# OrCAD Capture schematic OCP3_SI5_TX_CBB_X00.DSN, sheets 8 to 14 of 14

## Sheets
8 PAGE08 - POWER SEQUENCE: size Custom
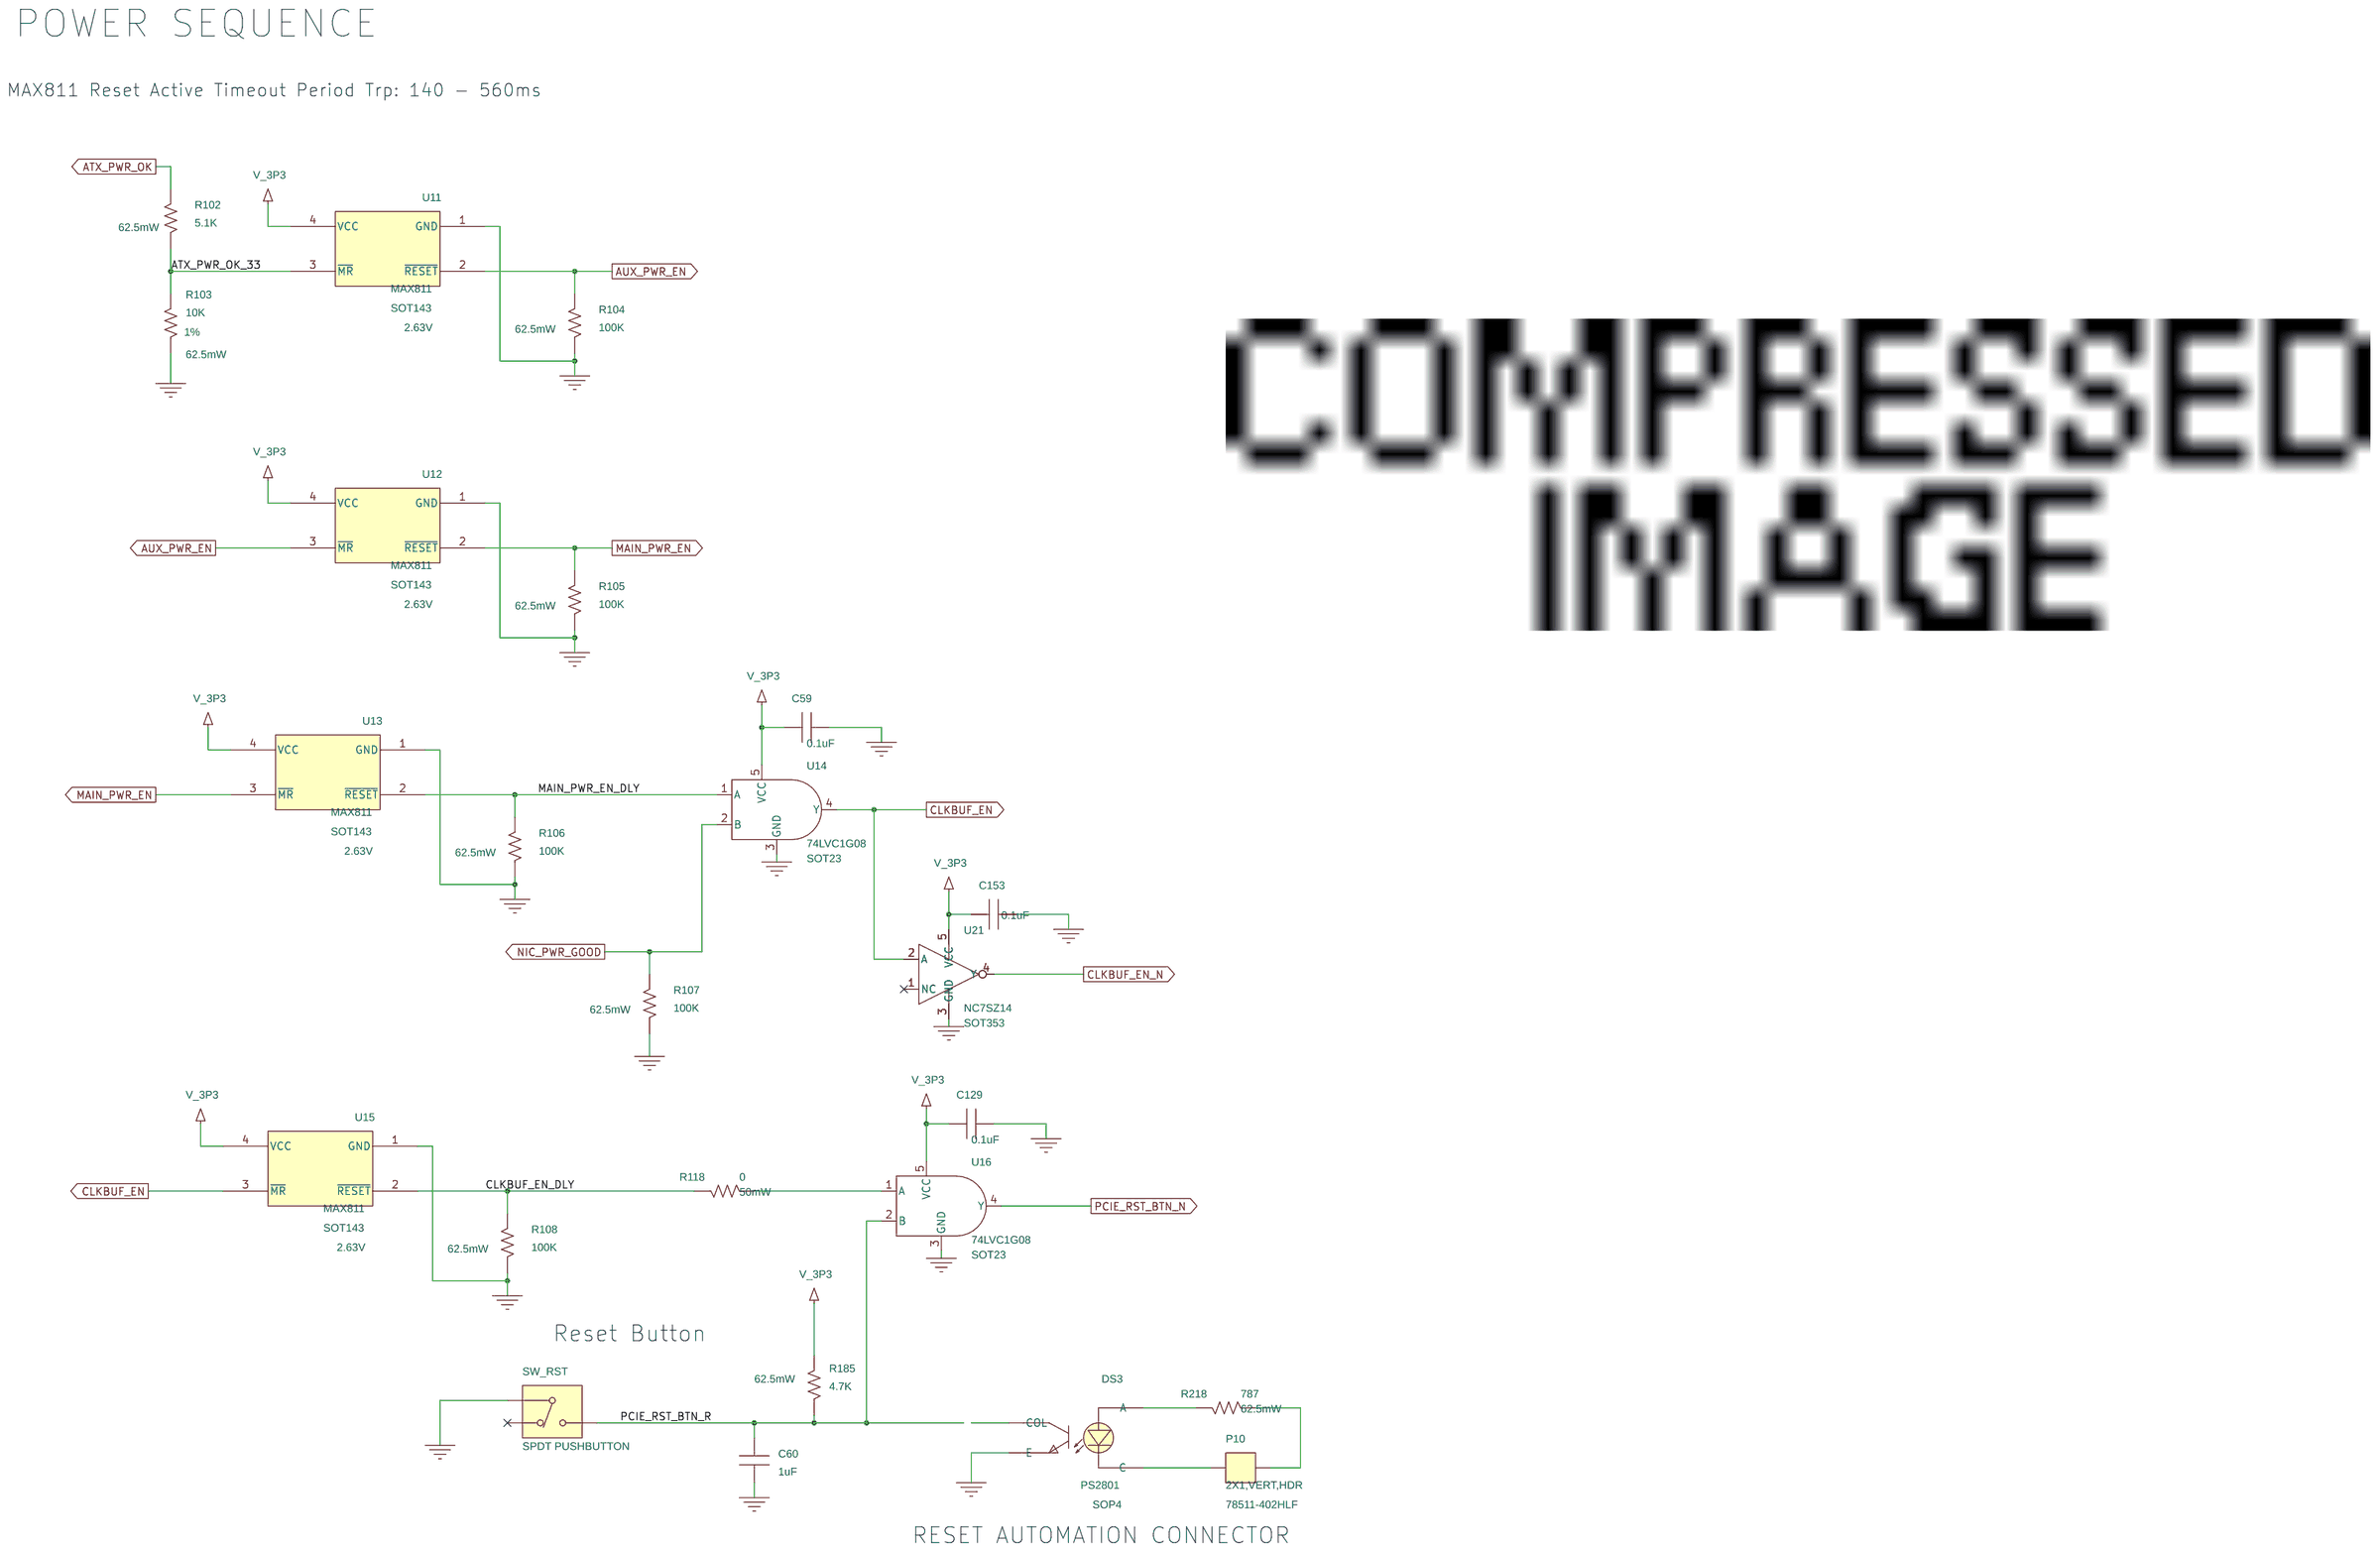
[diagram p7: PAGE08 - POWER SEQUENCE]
9 PAGE09 - PCIE LANES 0-3: size Custom
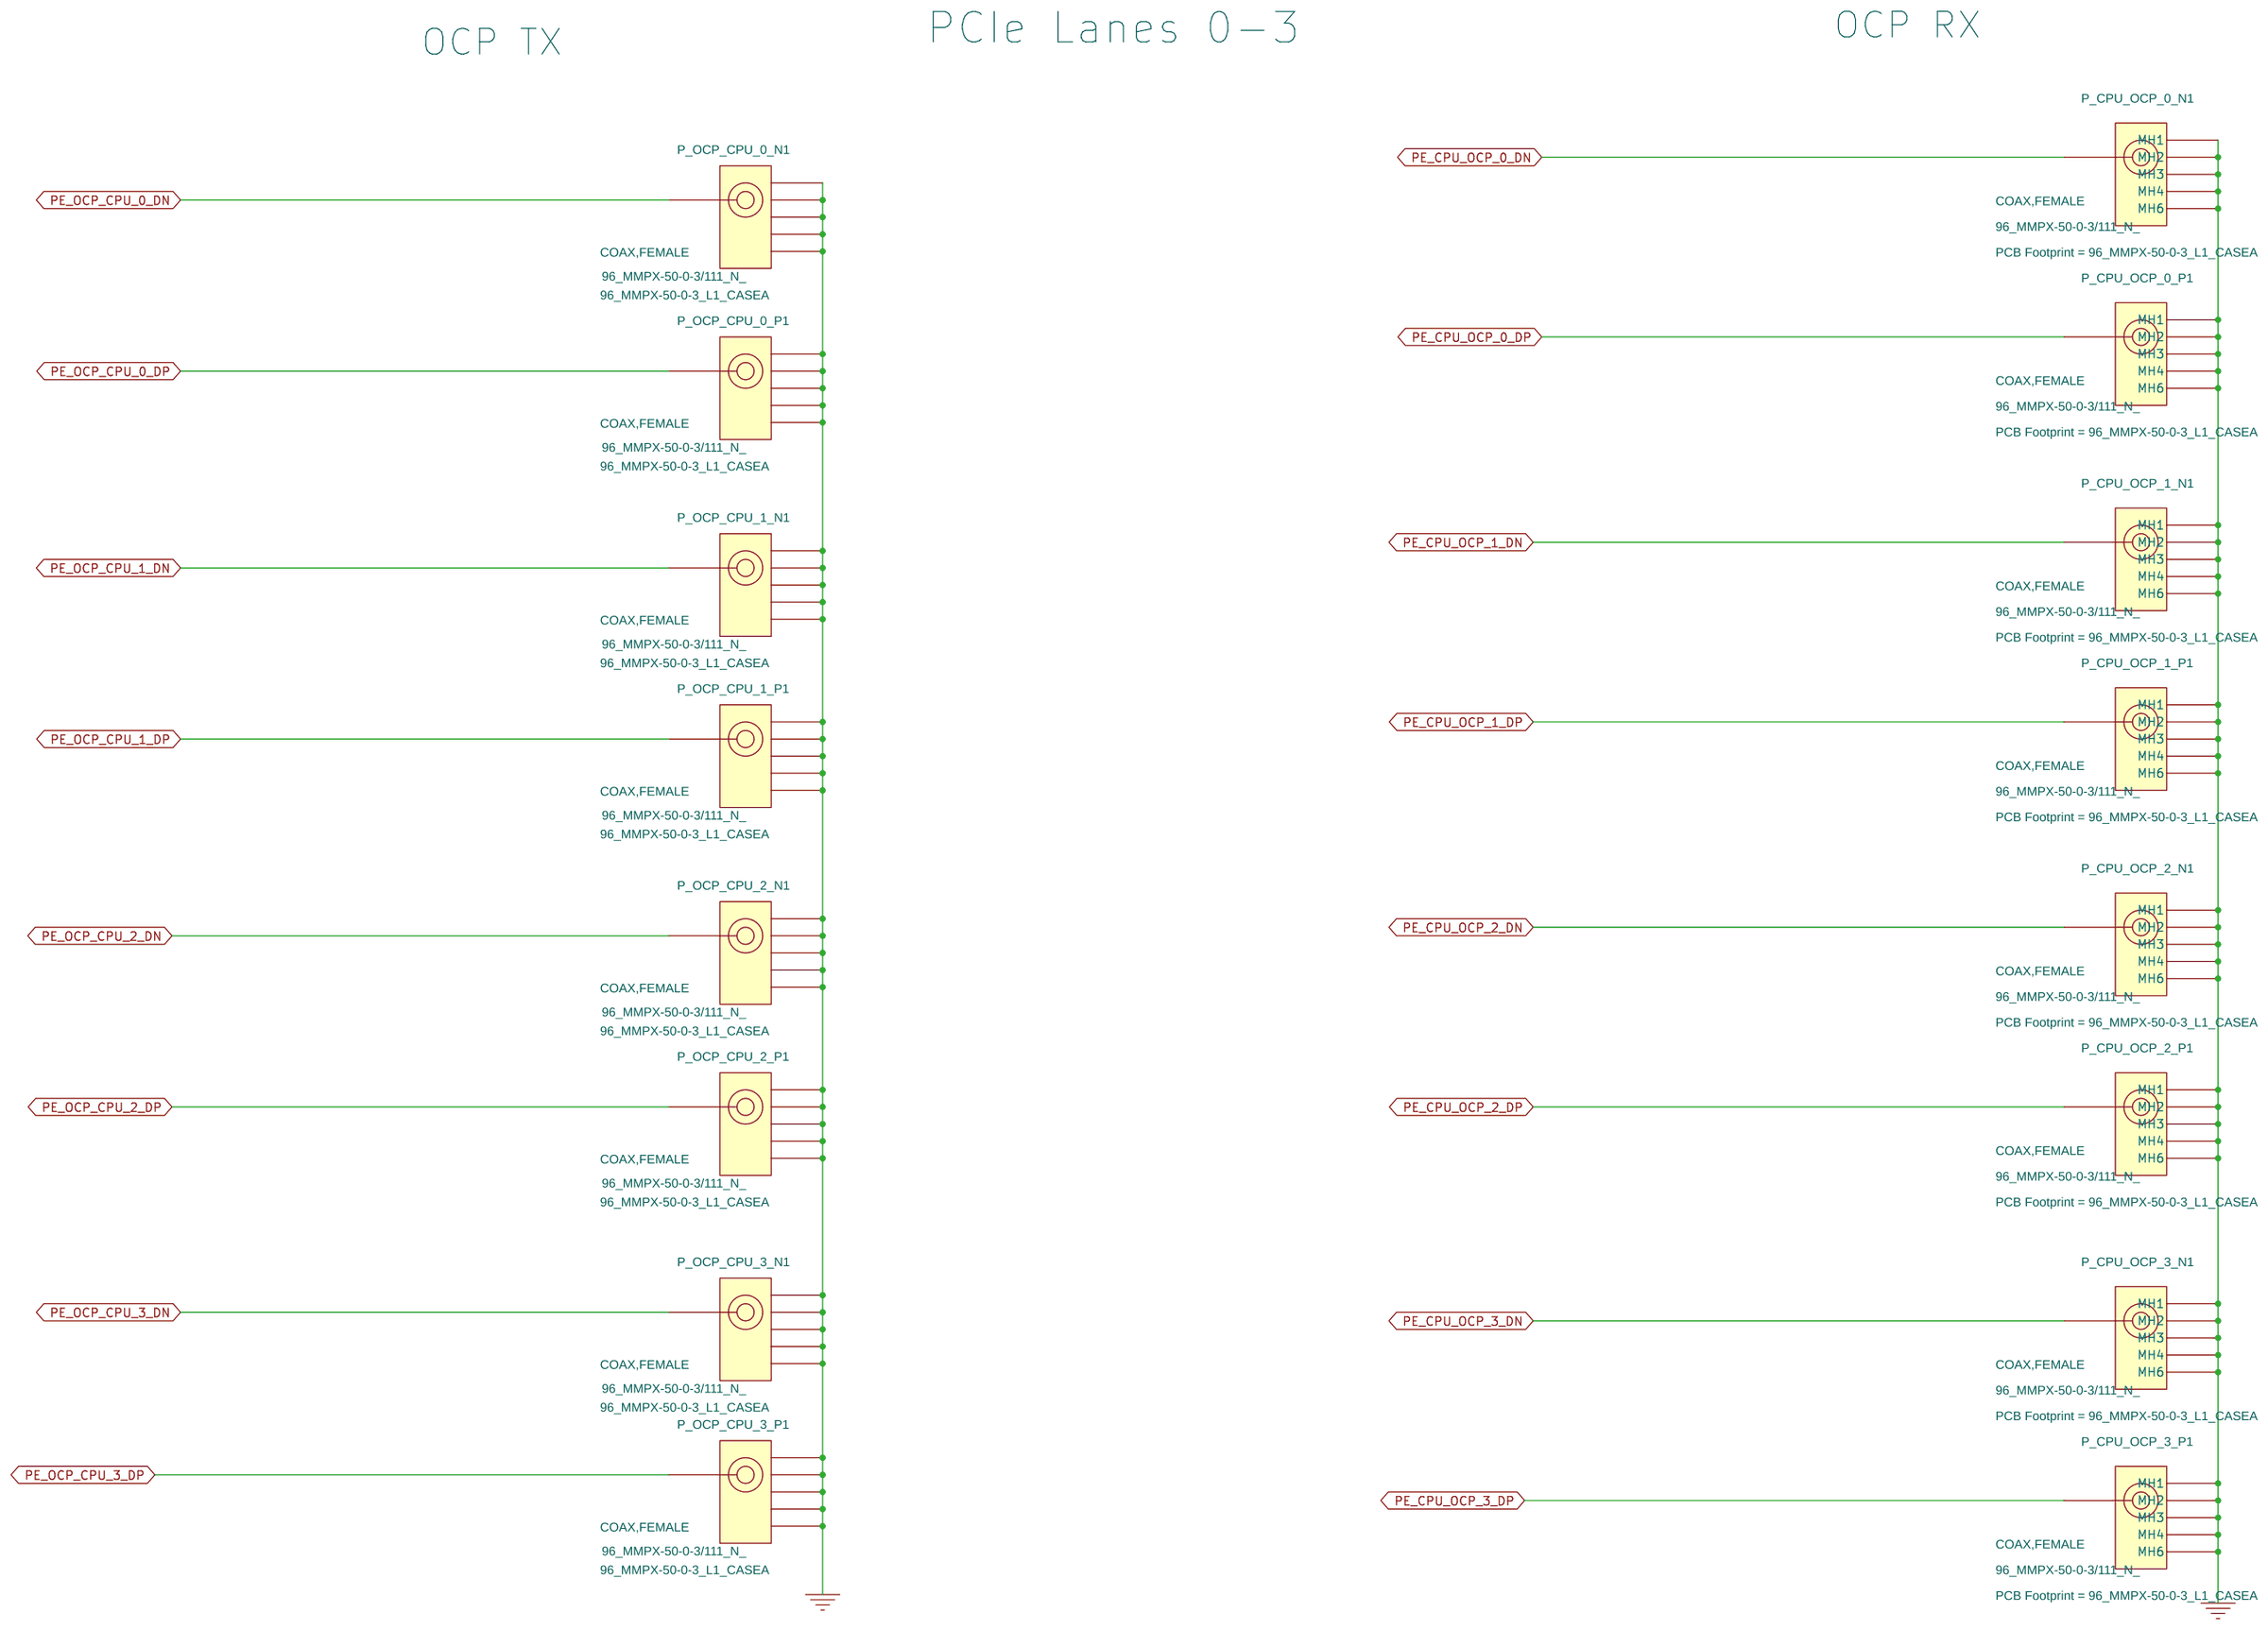
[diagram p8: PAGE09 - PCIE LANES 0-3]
10 PAGE10 - PCIE LANES 4-7: size Custom
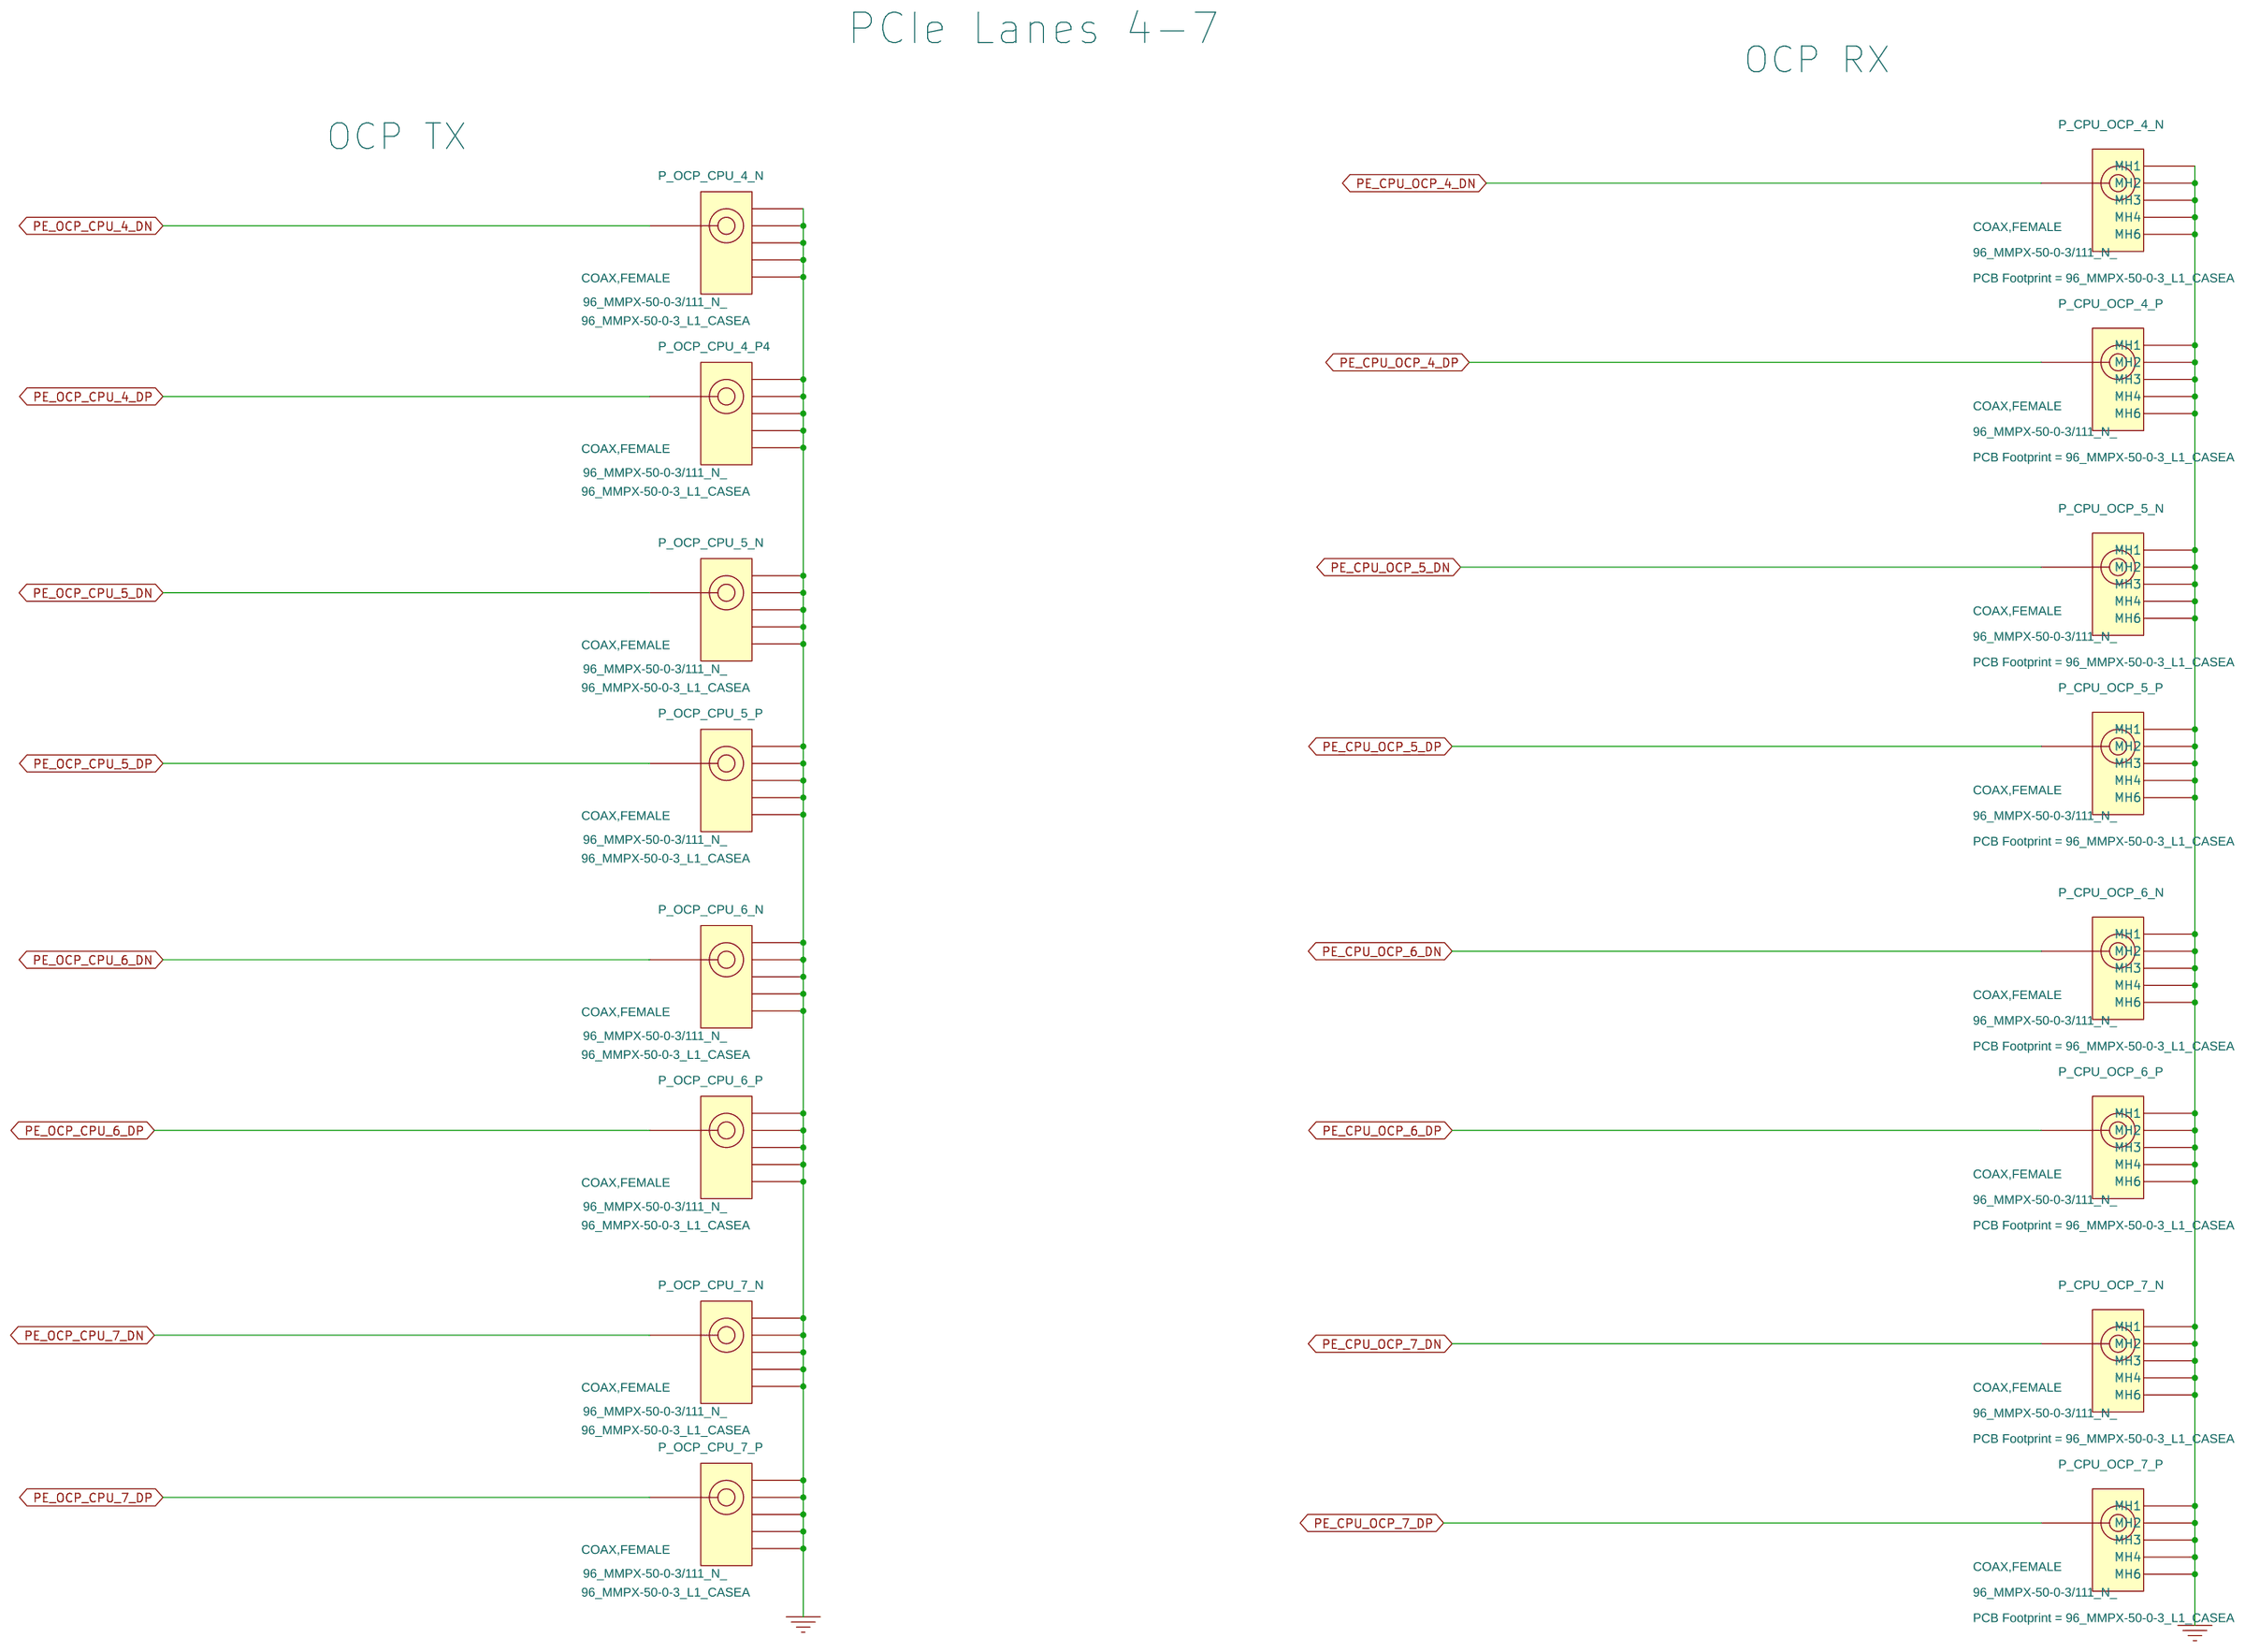
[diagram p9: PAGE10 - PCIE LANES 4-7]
11 PAGE11 - PCIE LANES 8-11: size Custom
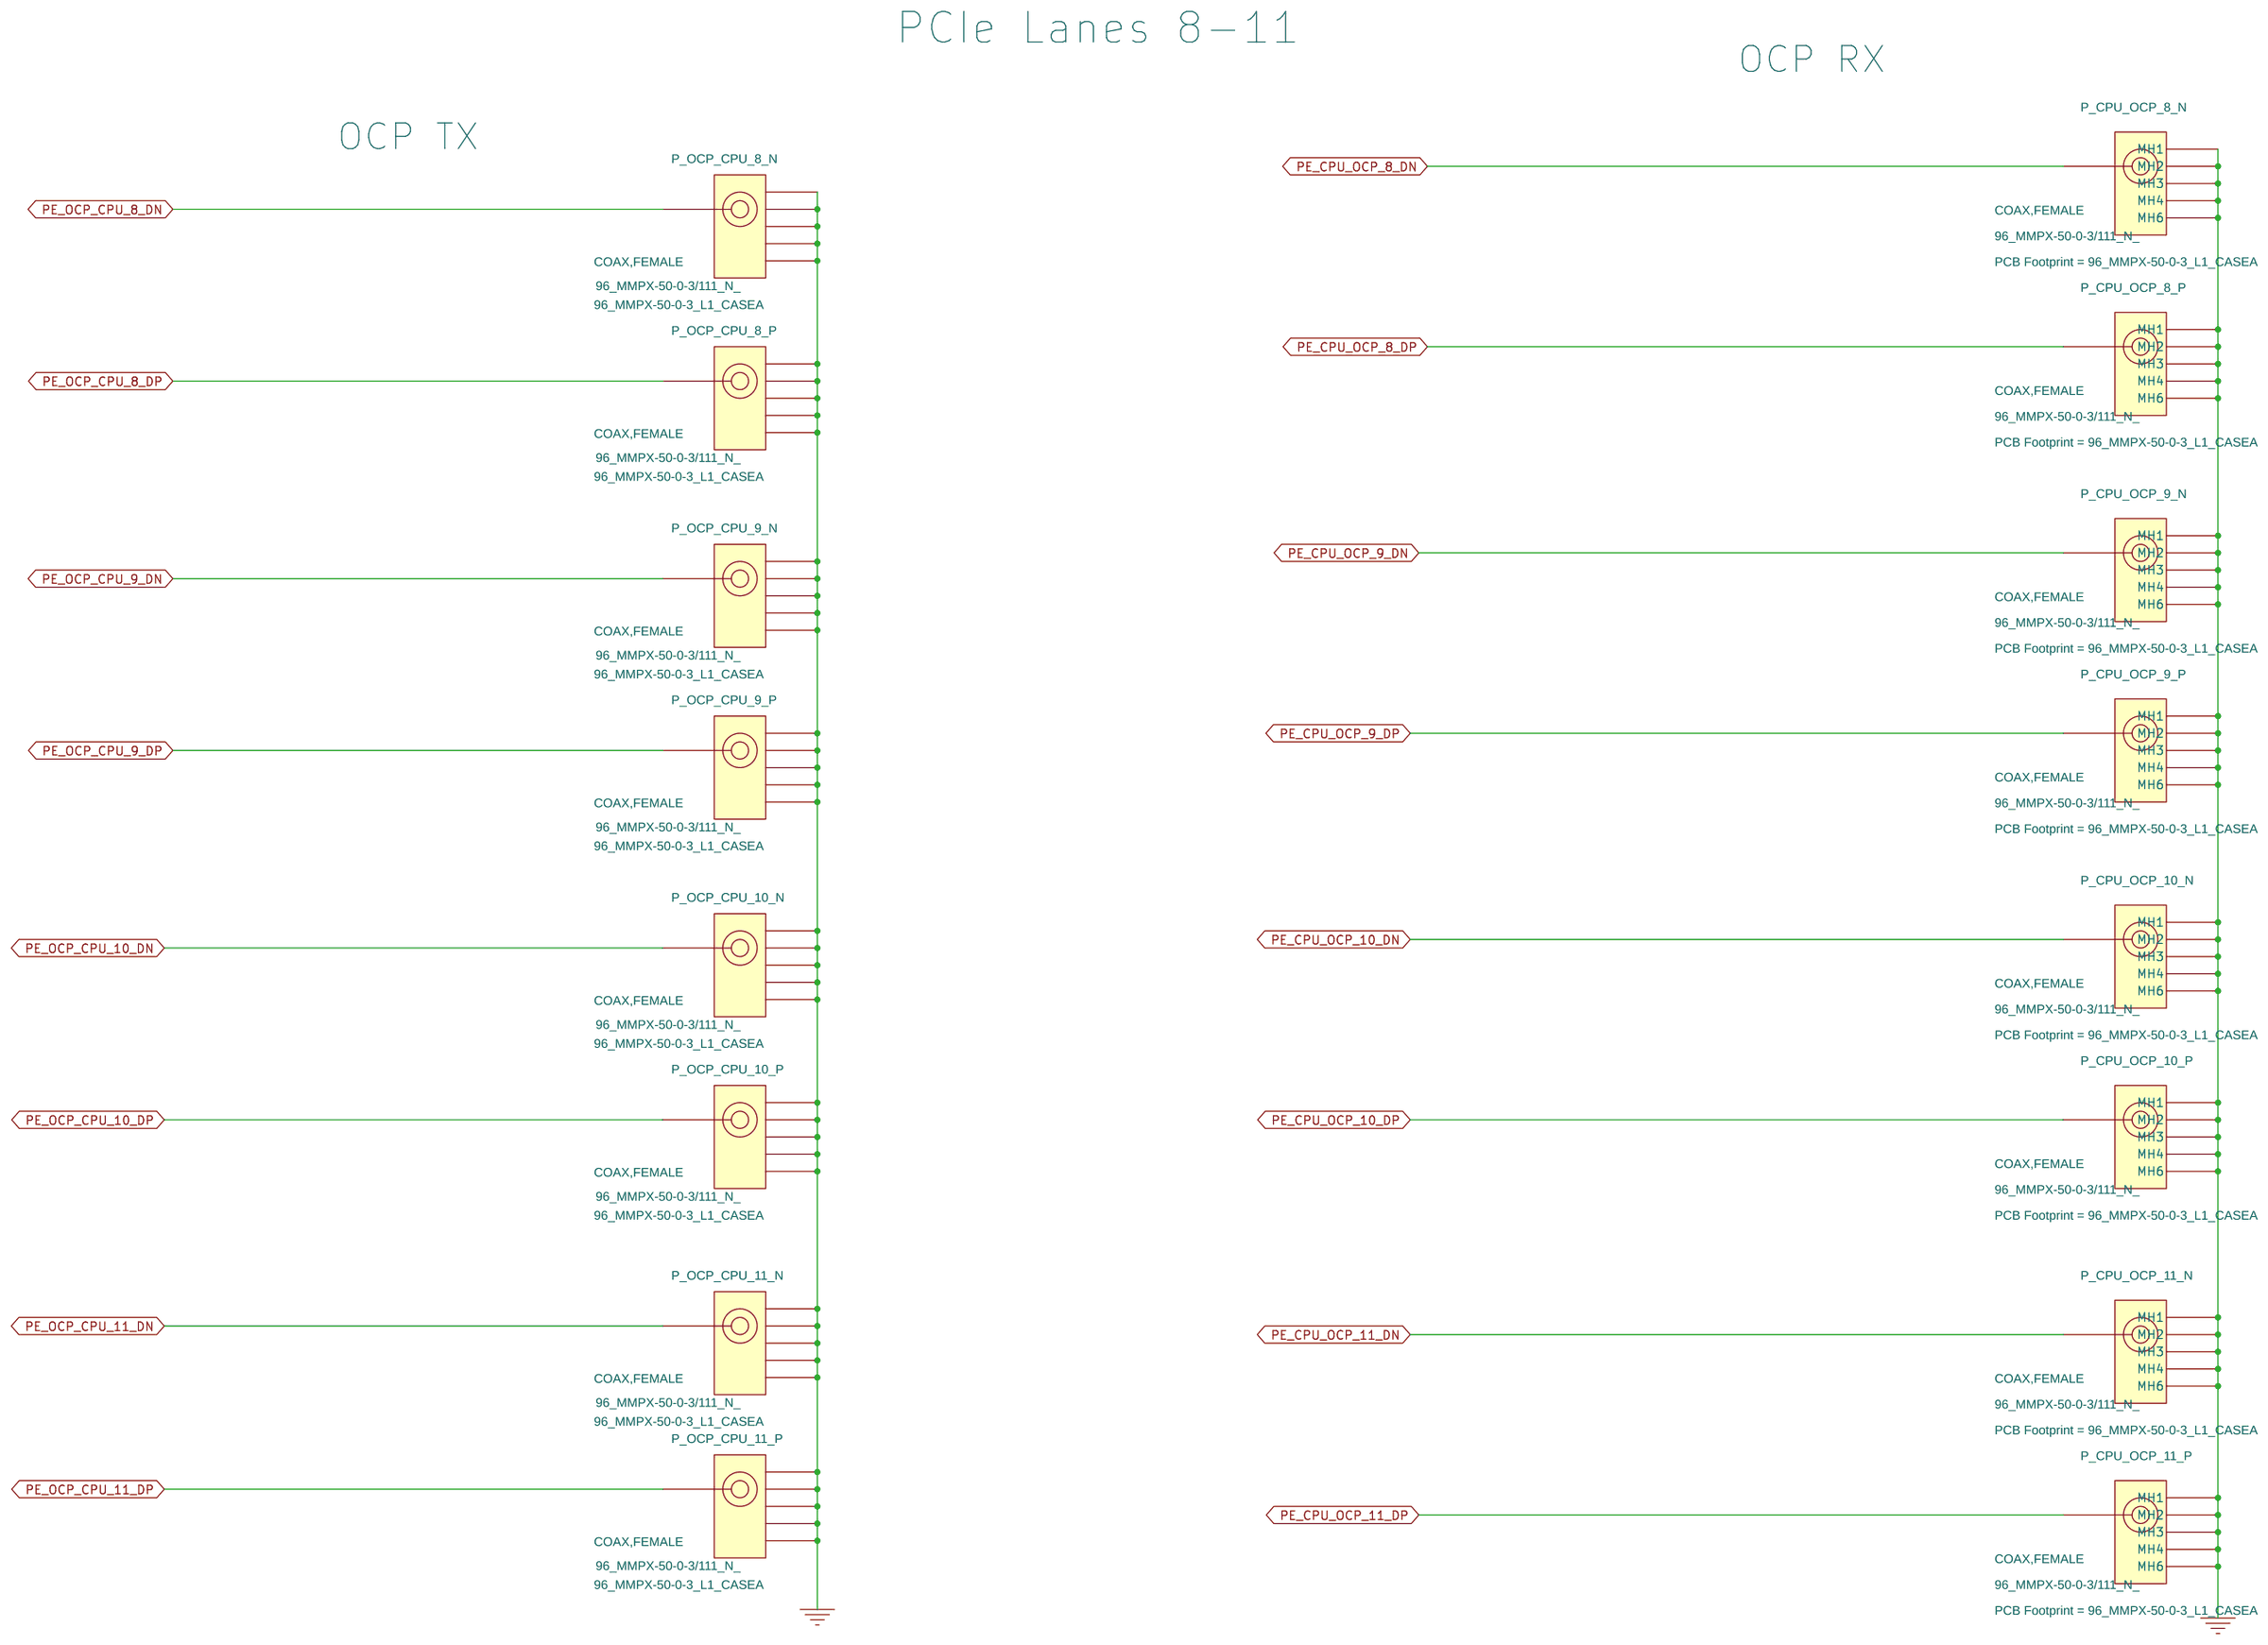
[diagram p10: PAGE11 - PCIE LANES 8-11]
12 PAGE12 - PCIE LANES 12-15: size Custom
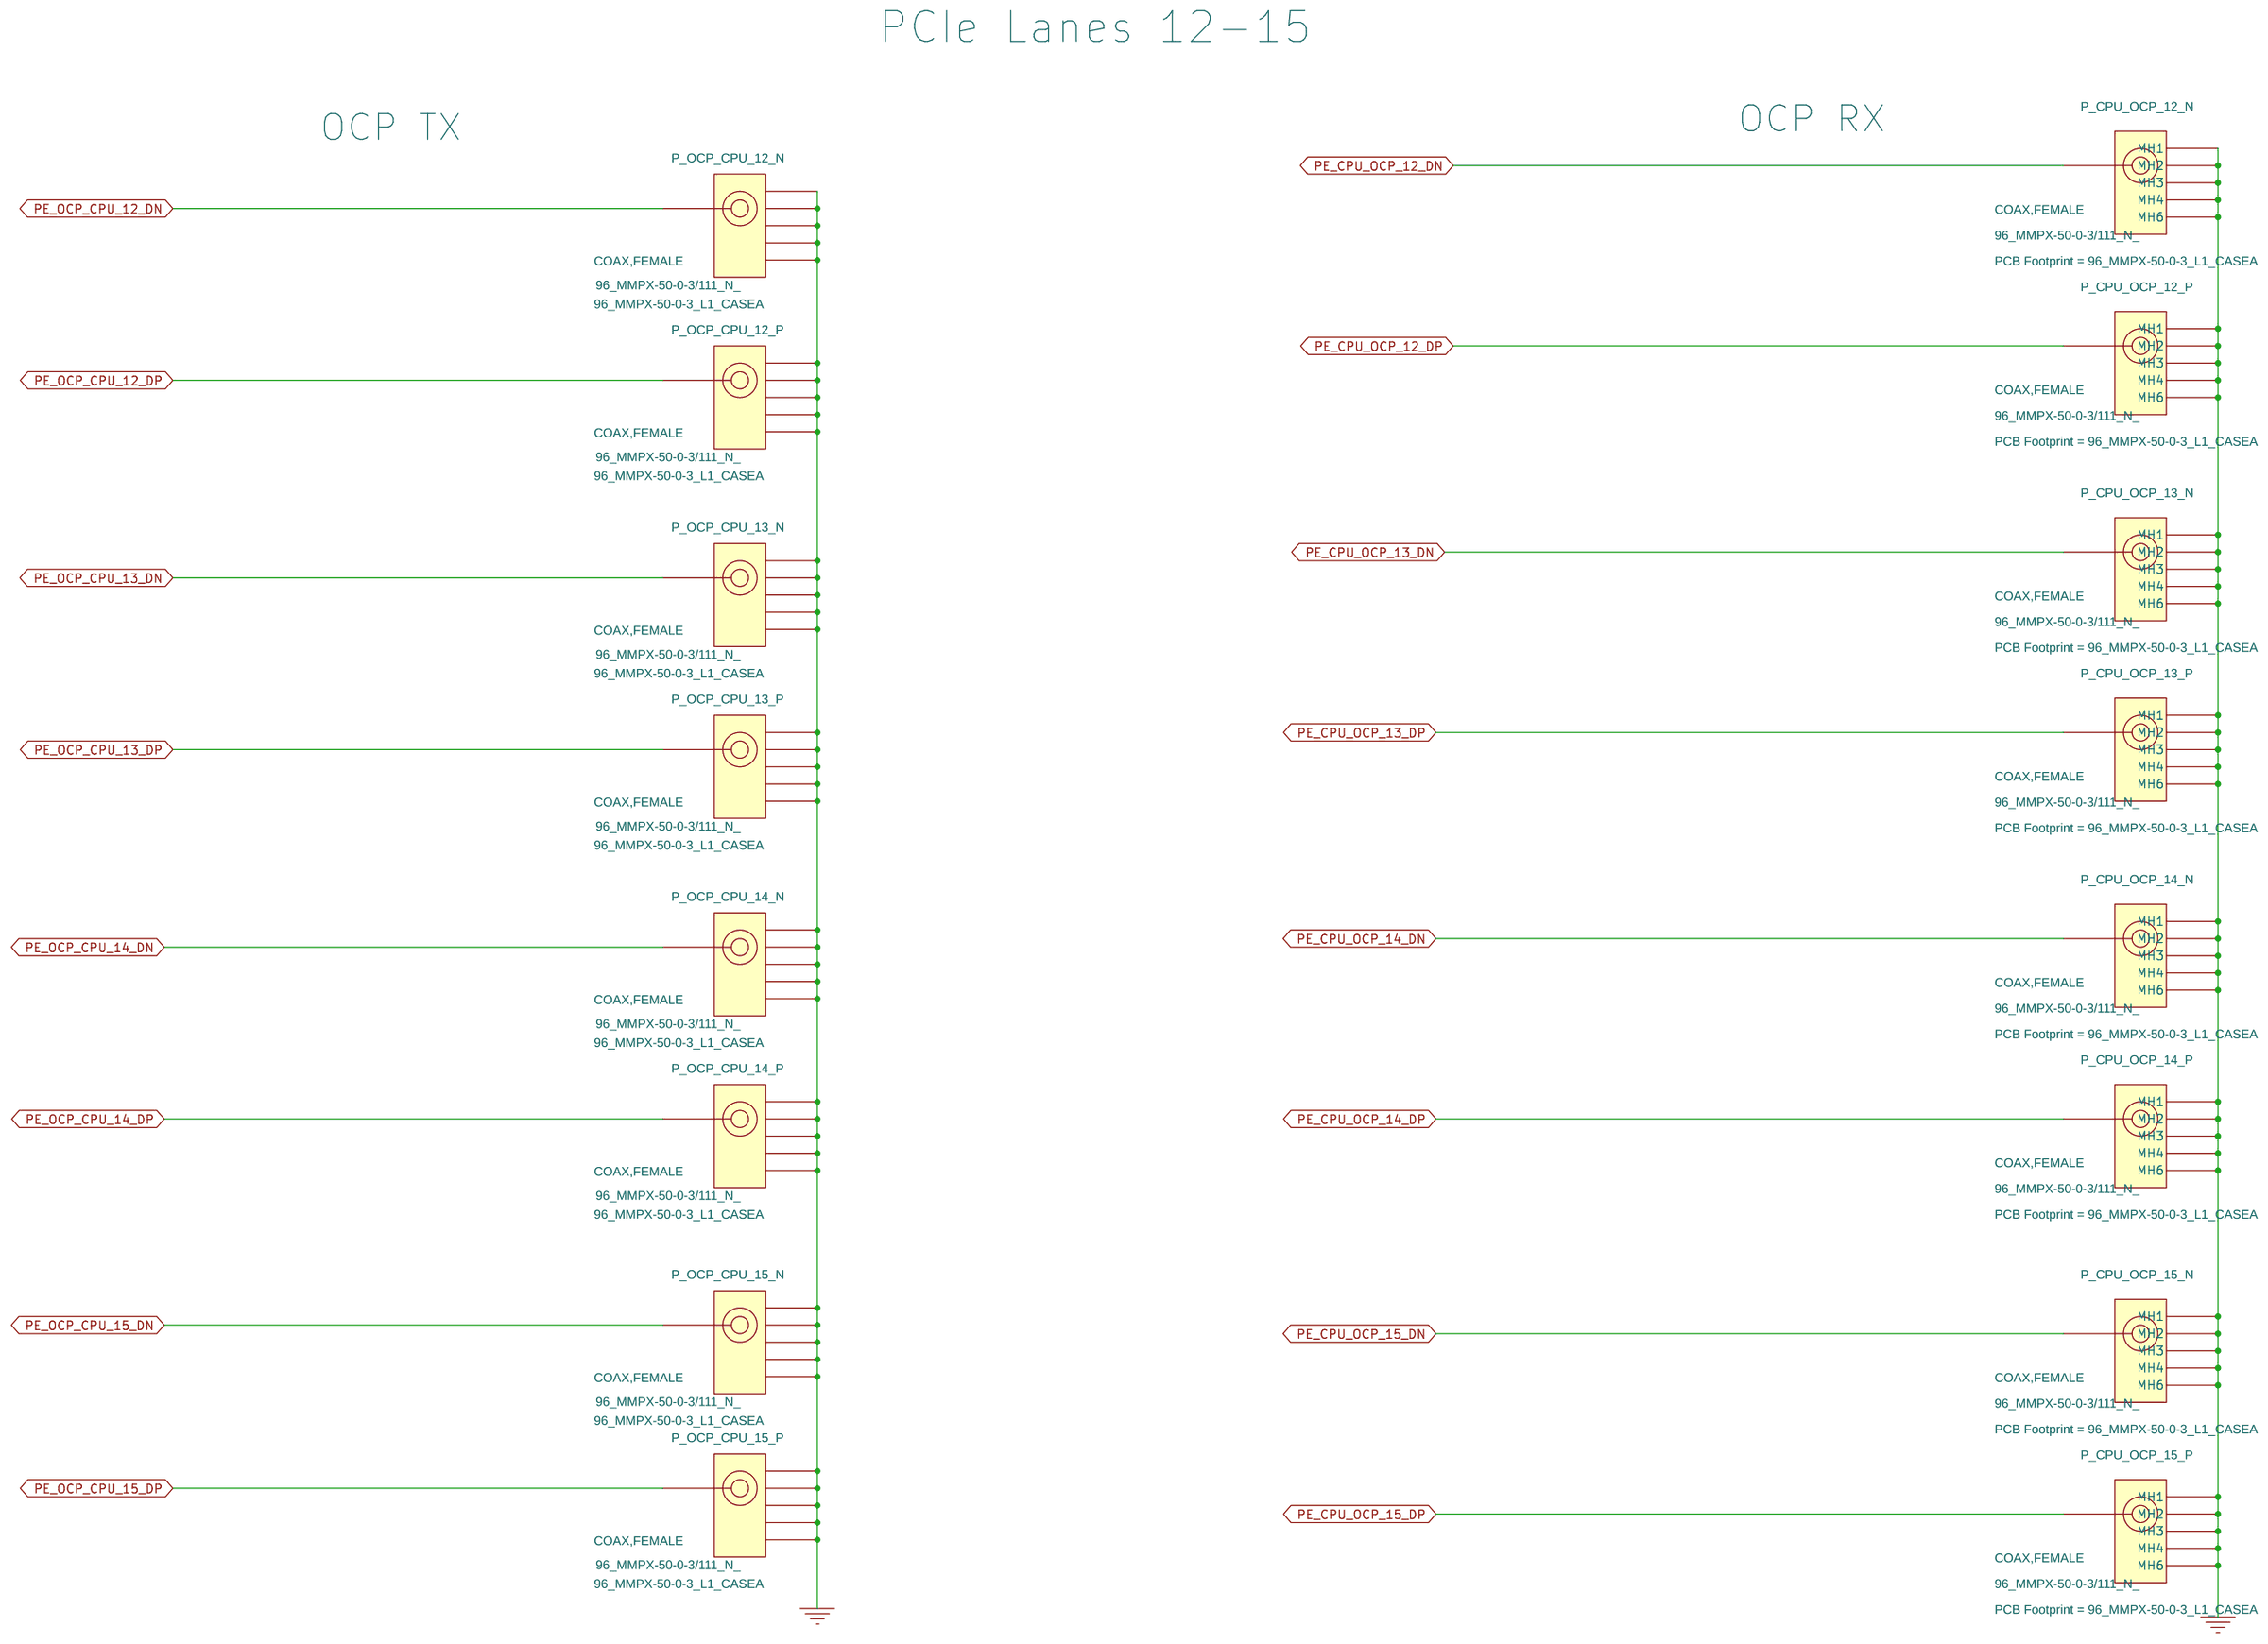
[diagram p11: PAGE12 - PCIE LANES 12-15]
13 PAGE13 - COUPONS AND SMAS: size Custom
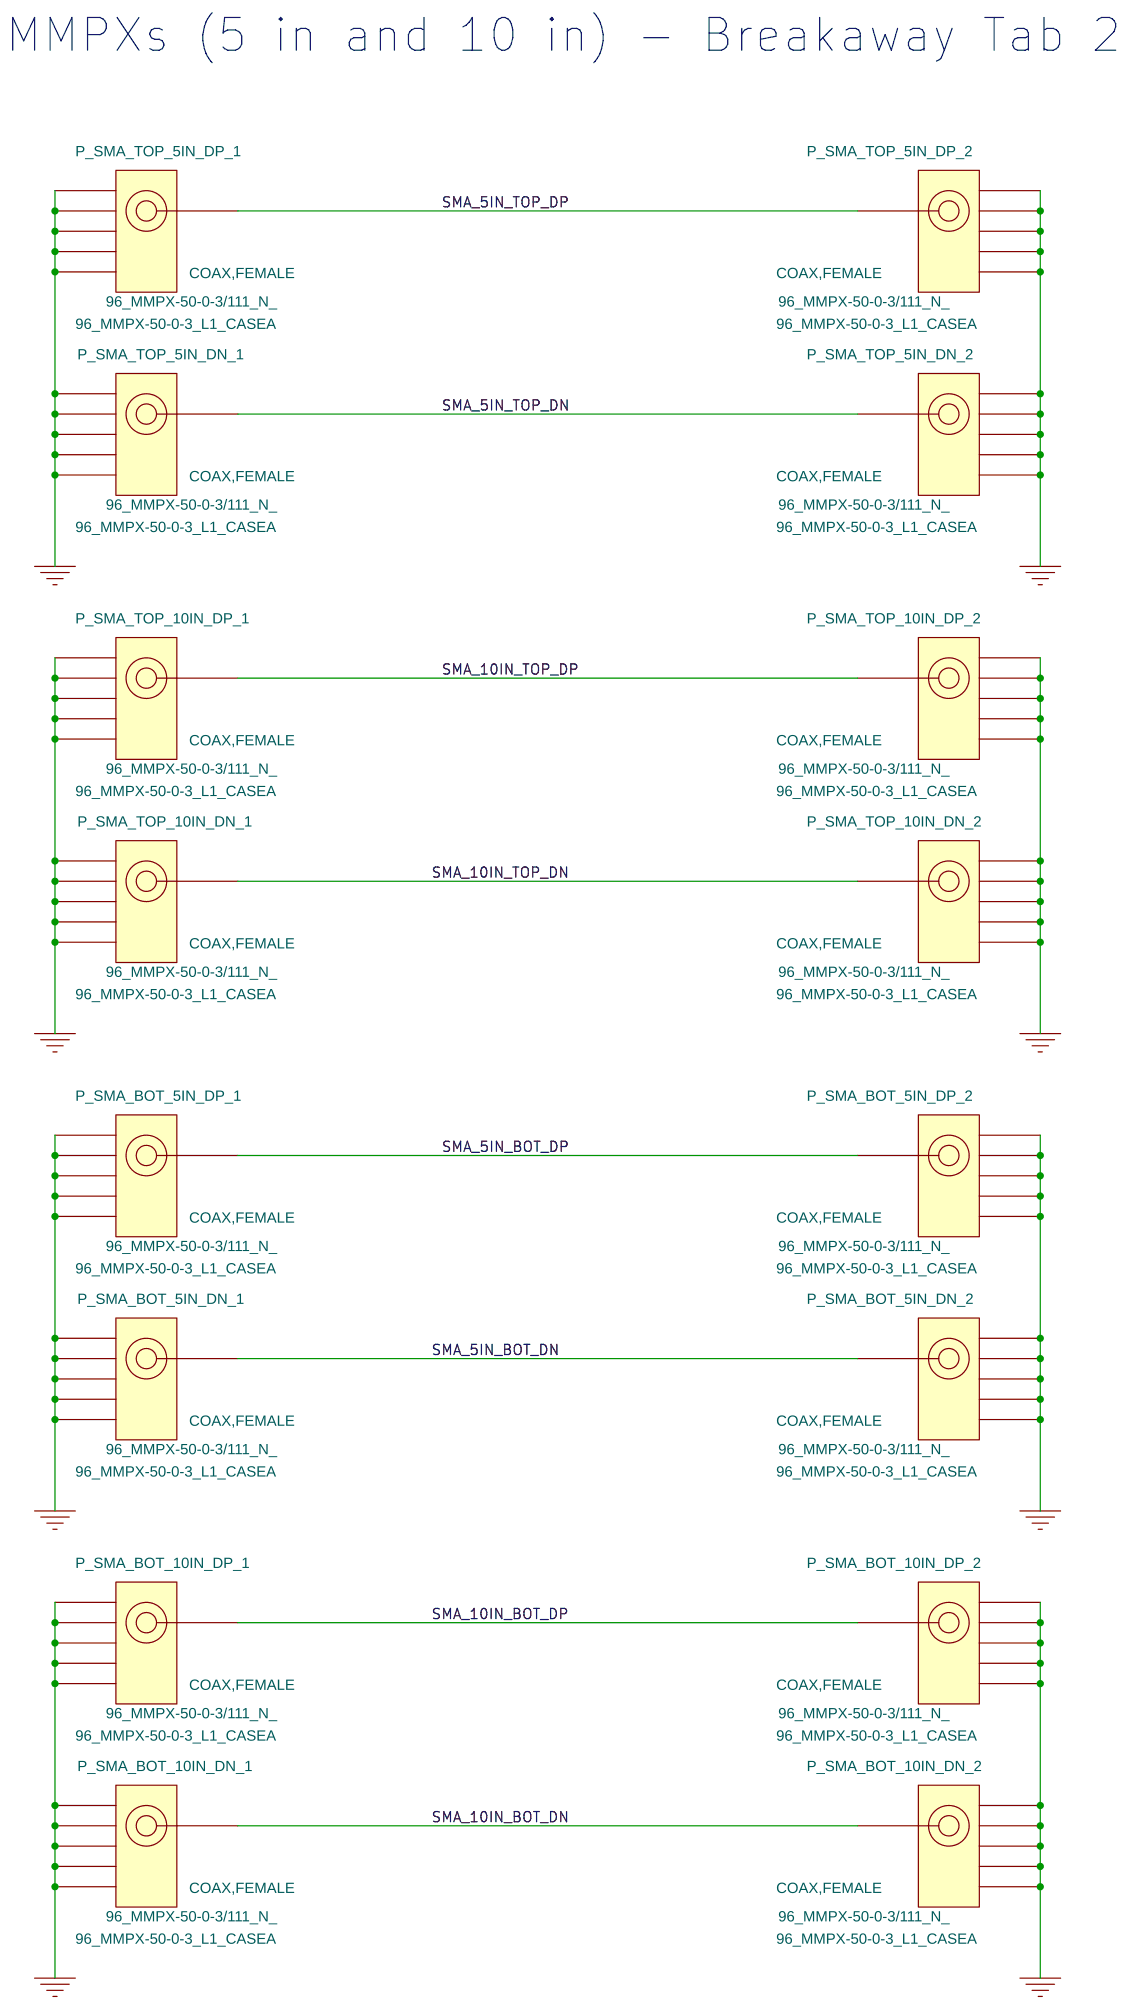
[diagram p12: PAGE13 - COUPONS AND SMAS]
14 PAGE14 - CBB CALIBRATION BOARD: size Custom
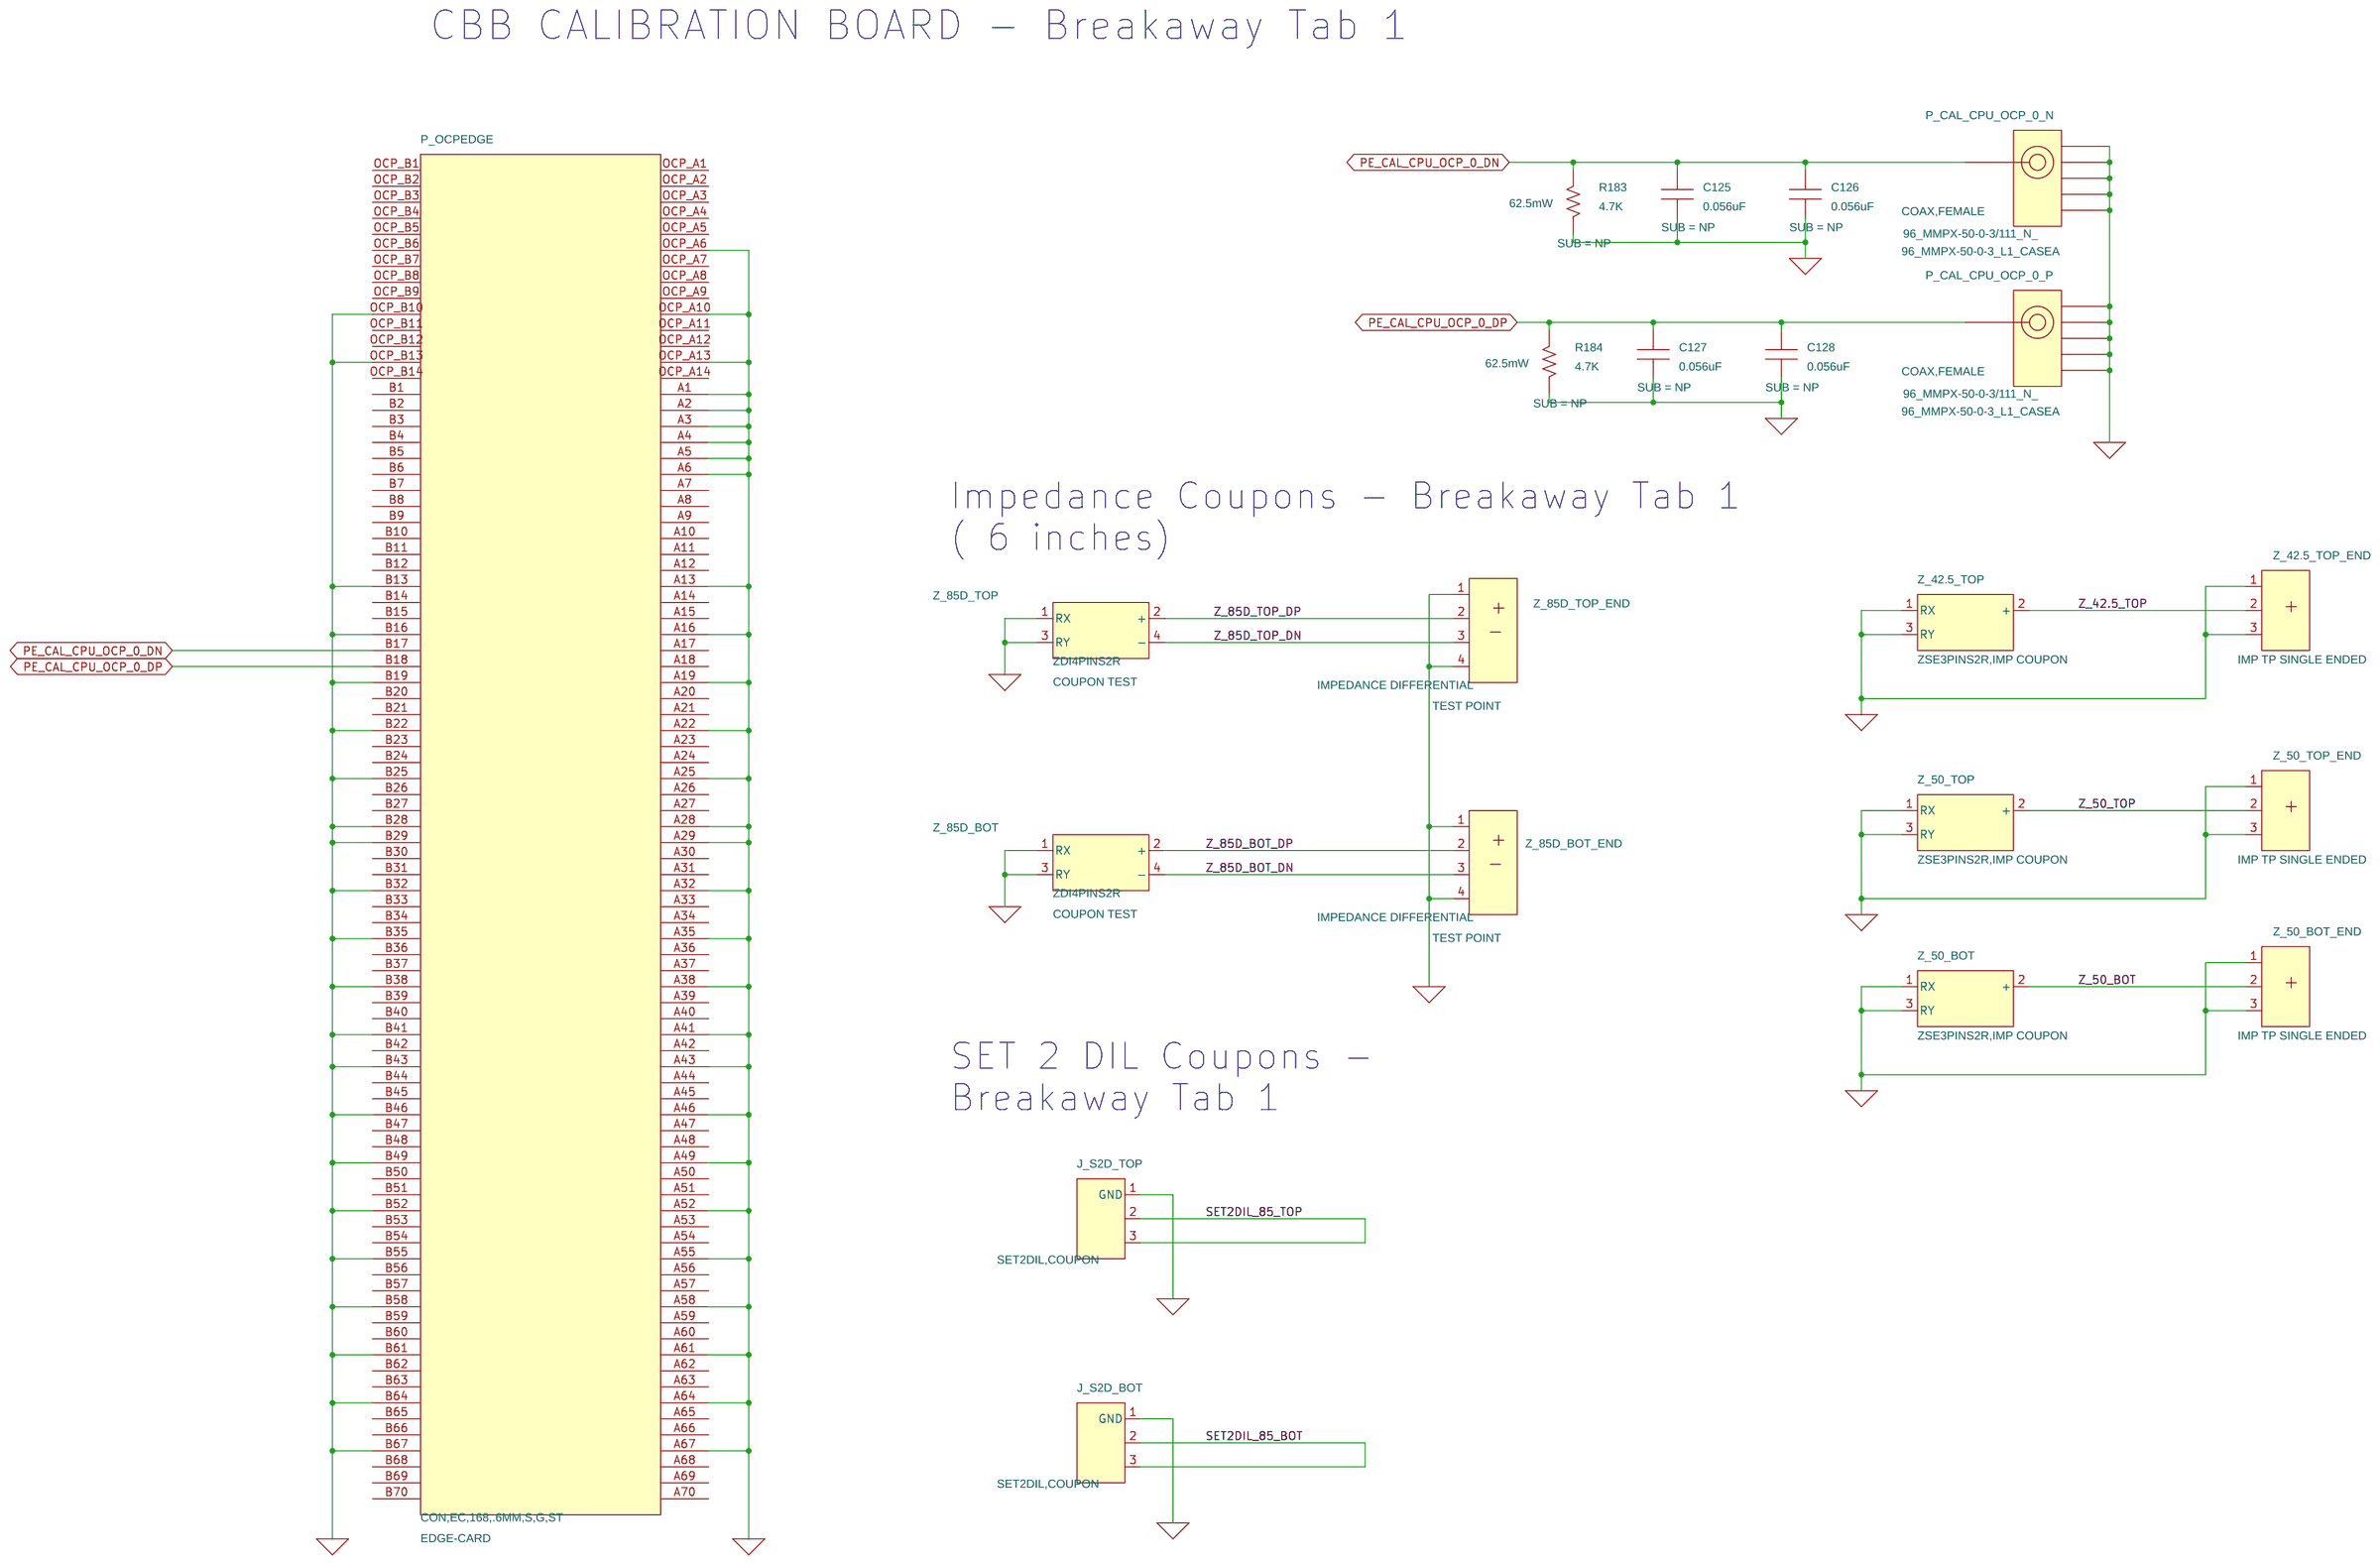
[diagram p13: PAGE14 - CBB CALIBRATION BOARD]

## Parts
sheet PAGE08 - POWER SEQUENCE
C59  0.1uF  [C0201]
C60  1uF  [C0603]
C129  0.1uF  [C0201]
C153  0.1uF  [C0201]
DS3  PS2801  [SOIC127P700X230_4N]
P10  2X1,VERT,HDR  [BERG1X2]
R102  5.1K  [R0402]
R103  10K  [R0402]
R104  100K  [R0402]
R105  100K  [R0402]
R106  100K  [R0402]
R107  100K  [R0402]
R108  100K  [R0402]
R118  0  [R0201]
R185  4.7K  [R0402]
R218  787  [R0402]
SW_RST  SPDT PUSHBUTTON  [SW3PSMRA_2SH]
U11  MAX811  [SOT192P237X122_4N]
U12  MAX811  [SOT192P237X122_4N]
U13  MAX811  [SOT192P237X122_4N]
U14  74LVC1G08  [SOT95P280X145_5N]
U15  MAX811  [SOT192P237X122_4N]
U16  74LVC1G08  [SOT95P280X145_5N]
U21  NC7SZ14  [SOT65P210X110_5L]
sheet PAGE09 - PCIE LANES 0-3
P_CPU_OCP_0_N1  COAX,FEMALE  [96_MMPX-50-0-3_L1_CASEA]
P_CPU_OCP_0_P1  COAX,FEMALE  [96_MMPX-50-0-3_L1_CASEA]
P_CPU_OCP_1_N1  COAX,FEMALE  [96_MMPX-50-0-3_L1_CASEA]
P_CPU_OCP_1_P1  COAX,FEMALE  [96_MMPX-50-0-3_L1_CASEA]
P_CPU_OCP_2_N1  COAX,FEMALE  [96_MMPX-50-0-3_L1_CASEA]
P_CPU_OCP_2_P1  COAX,FEMALE  [96_MMPX-50-0-3_L1_CASEA]
P_CPU_OCP_3_N1  COAX,FEMALE  [96_MMPX-50-0-3_L1_CASEA]
P_CPU_OCP_3_P1  COAX,FEMALE  [96_MMPX-50-0-3_L1_CASEA]
P_OCP_CPU_0_N1  COAX,FEMALE  [96_MMPX-50-0-3_L1_CASEA]
P_OCP_CPU_0_P1  COAX,FEMALE  [96_MMPX-50-0-3_L1_CASEA]
P_OCP_CPU_1_N1  COAX,FEMALE  [96_MMPX-50-0-3_L1_CASEA]
P_OCP_CPU_1_P1  COAX,FEMALE  [96_MMPX-50-0-3_L1_CASEA]
P_OCP_CPU_2_N1  COAX,FEMALE  [96_MMPX-50-0-3_L1_CASEA]
P_OCP_CPU_2_P1  COAX,FEMALE  [96_MMPX-50-0-3_L1_CASEA]
P_OCP_CPU_3_N1  COAX,FEMALE  [96_MMPX-50-0-3_L1_CASEA]
P_OCP_CPU_3_P1  COAX,FEMALE  [96_MMPX-50-0-3_L1_CASEA]
sheet PAGE10 - PCIE LANES 4-7
P_CPU_OCP_4_N  COAX,FEMALE  [96_MMPX-50-0-3_L1_CASEA]
P_CPU_OCP_4_P  COAX,FEMALE  [96_MMPX-50-0-3_L1_CASEA]
P_CPU_OCP_5_N  COAX,FEMALE  [96_MMPX-50-0-3_L1_CASEA]
P_CPU_OCP_5_P  COAX,FEMALE  [96_MMPX-50-0-3_L1_CASEA]
P_CPU_OCP_6_N  COAX,FEMALE  [96_MMPX-50-0-3_L1_CASEA]
P_CPU_OCP_6_P  COAX,FEMALE  [96_MMPX-50-0-3_L1_CASEA]
P_CPU_OCP_7_N  COAX,FEMALE  [96_MMPX-50-0-3_L1_CASEA]
P_CPU_OCP_7_P  COAX,FEMALE  [96_MMPX-50-0-3_L1_CASEA]
P_OCP_CPU_4_N  COAX,FEMALE  [96_MMPX-50-0-3_L1_CASEA]
P_OCP_CPU_4_P4  COAX,FEMALE  [96_MMPX-50-0-3_L1_CASEA]
P_OCP_CPU_5_N  COAX,FEMALE  [96_MMPX-50-0-3_L1_CASEA]
P_OCP_CPU_5_P  COAX,FEMALE  [96_MMPX-50-0-3_L1_CASEA]
P_OCP_CPU_6_N  COAX,FEMALE  [96_MMPX-50-0-3_L1_CASEA]
P_OCP_CPU_6_P  COAX,FEMALE  [96_MMPX-50-0-3_L1_CASEA]
P_OCP_CPU_7_N  COAX,FEMALE  [96_MMPX-50-0-3_L1_CASEA]
P_OCP_CPU_7_P  COAX,FEMALE  [96_MMPX-50-0-3_L1_CASEA]
sheet PAGE11 - PCIE LANES 8-11
P_CPU_OCP_8_N  COAX,FEMALE  [96_MMPX-50-0-3_L1_CASEA]
P_CPU_OCP_8_P  COAX,FEMALE  [96_MMPX-50-0-3_L1_CASEA]
P_CPU_OCP_9_N  COAX,FEMALE  [96_MMPX-50-0-3_L1_CASEA]
P_CPU_OCP_9_P  COAX,FEMALE  [96_MMPX-50-0-3_L1_CASEA]
P_CPU_OCP_10_N  COAX,FEMALE  [96_MMPX-50-0-3_L1_CASEA]
P_CPU_OCP_10_P  COAX,FEMALE  [96_MMPX-50-0-3_L1_CASEA]
P_CPU_OCP_11_N  COAX,FEMALE  [96_MMPX-50-0-3_L1_CASEA]
P_CPU_OCP_11_P  COAX,FEMALE  [96_MMPX-50-0-3_L1_CASEA]
P_OCP_CPU_8_N  COAX,FEMALE  [96_MMPX-50-0-3_L1_CASEA]
P_OCP_CPU_8_P  COAX,FEMALE  [96_MMPX-50-0-3_L1_CASEA]
P_OCP_CPU_9_N  COAX,FEMALE  [96_MMPX-50-0-3_L1_CASEA]
P_OCP_CPU_9_P  COAX,FEMALE  [96_MMPX-50-0-3_L1_CASEA]
P_OCP_CPU_10_N  COAX,FEMALE  [96_MMPX-50-0-3_L1_CASEA]
P_OCP_CPU_10_P  COAX,FEMALE  [96_MMPX-50-0-3_L1_CASEA]
P_OCP_CPU_11_N  COAX,FEMALE  [96_MMPX-50-0-3_L1_CASEA]
P_OCP_CPU_11_P  COAX,FEMALE  [96_MMPX-50-0-3_L1_CASEA]
sheet PAGE12 - PCIE LANES 12-15
P_CPU_OCP_12_N  COAX,FEMALE  [96_MMPX-50-0-3_L1_CASEA]
P_CPU_OCP_12_P  COAX,FEMALE  [96_MMPX-50-0-3_L1_CASEA]
P_CPU_OCP_13_N  COAX,FEMALE  [96_MMPX-50-0-3_L1_CASEA]
P_CPU_OCP_13_P  COAX,FEMALE  [96_MMPX-50-0-3_L1_CASEA]
P_CPU_OCP_14_N  COAX,FEMALE  [96_MMPX-50-0-3_L1_CASEA]
P_CPU_OCP_14_P  COAX,FEMALE  [96_MMPX-50-0-3_L1_CASEA]
P_CPU_OCP_15_N  COAX,FEMALE  [96_MMPX-50-0-3_L1_CASEA]
P_CPU_OCP_15_P  COAX,FEMALE  [96_MMPX-50-0-3_L1_CASEA]
P_OCP_CPU_12_N  COAX,FEMALE  [96_MMPX-50-0-3_L1_CASEA]
P_OCP_CPU_12_P  COAX,FEMALE  [96_MMPX-50-0-3_L1_CASEA]
P_OCP_CPU_13_N  COAX,FEMALE  [96_MMPX-50-0-3_L1_CASEA]
P_OCP_CPU_13_P  COAX,FEMALE  [96_MMPX-50-0-3_L1_CASEA]
P_OCP_CPU_14_N  COAX,FEMALE  [96_MMPX-50-0-3_L1_CASEA]
P_OCP_CPU_14_P  COAX,FEMALE  [96_MMPX-50-0-3_L1_CASEA]
P_OCP_CPU_15_N  COAX,FEMALE  [96_MMPX-50-0-3_L1_CASEA]
P_OCP_CPU_15_P  COAX,FEMALE  [96_MMPX-50-0-3_L1_CASEA]
sheet PAGE13 - COUPONS AND SMAS
P_SMA_BOT_5IN_DN_1  COAX,FEMALE  [96_MMPX-50-0-3_L1_CASEA]
P_SMA_BOT_5IN_DN_2  COAX,FEMALE  [96_MMPX-50-0-3_L1_CASEA]
P_SMA_BOT_5IN_DP_1  COAX,FEMALE  [96_MMPX-50-0-3_L1_CASEA]
P_SMA_BOT_5IN_DP_2  COAX,FEMALE  [96_MMPX-50-0-3_L1_CASEA]
P_SMA_BOT_10IN_DN_1  COAX,FEMALE  [96_MMPX-50-0-3_L1_CASEA]
P_SMA_BOT_10IN_DN_2  COAX,FEMALE  [96_MMPX-50-0-3_L1_CASEA]
P_SMA_BOT_10IN_DP_1  COAX,FEMALE  [96_MMPX-50-0-3_L1_CASEA]
P_SMA_BOT_10IN_DP_2  COAX,FEMALE  [96_MMPX-50-0-3_L1_CASEA]
P_SMA_TOP_5IN_DN_1  COAX,FEMALE  [96_MMPX-50-0-3_L1_CASEA]
P_SMA_TOP_5IN_DN_2  COAX,FEMALE  [96_MMPX-50-0-3_L1_CASEA]
P_SMA_TOP_5IN_DP_1  COAX,FEMALE  [96_MMPX-50-0-3_L1_CASEA]
P_SMA_TOP_5IN_DP_2  COAX,FEMALE  [96_MMPX-50-0-3_L1_CASEA]
P_SMA_TOP_10IN_DN_1  COAX,FEMALE  [96_MMPX-50-0-3_L1_CASEA]
P_SMA_TOP_10IN_DN_2  COAX,FEMALE  [96_MMPX-50-0-3_L1_CASEA]
P_SMA_TOP_10IN_DP_1  COAX,FEMALE  [96_MMPX-50-0-3_L1_CASEA]
P_SMA_TOP_10IN_DP_2  COAX,FEMALE  [96_MMPX-50-0-3_L1_CASEA]
sheet PAGE14 - CBB CALIBRATION BOARD
C125  0.056uF  [C0402]
C126  0.056uF  [C0402]
C127  0.056uF  [C0402]
C128  0.056uF  [C0402]
J_S2D_BOT  SET2DIL,COUPON  [TP3_PPROBEB]
J_S2D_TOP  SET2DIL,COUPON  [TP3_PPROBEB]
P_CAL_CPU_OCP_0_N  COAX,FEMALE  [96_MMPX-50-0-3_L1_CASEA]
P_CAL_CPU_OCP_0_P  COAX,FEMALE  [96_MMPX-50-0-3_L1_CASEA]
P_OCPEDGE  CON,EC,168,.6MM,S,G,ST  [CON_AMP_EDGE_ME101681340131X]
R183  4.7K  [R0402]
R184  4.7K  [R0402]
Z_42.5_TOP  ZSE3PINS2R,IMP COUPON  [ZSE3PINS2R]
Z_42.5_TOP_END  IMP TP SINGLE ENDED  [IMP_TP_1X3_35P]
Z_50_BOT  ZSE3PINS2R,IMP COUPON  [ZSE3PINS2R]
Z_50_BOT_END  IMP TP SINGLE ENDED  [IMP_TP_1X3_35P]
Z_50_TOP  ZSE3PINS2R,IMP COUPON  [ZSE3PINS2R]
Z_50_TOP_END  IMP TP SINGLE ENDED  [IMP_TP_1X3_35P]
Z_85D_BOT  zdi4pins2r  [ZDI4PINS2R]
Z_85D_BOT_END  imp_tp_diff  [IMP_TP_1X4_35P]
Z_85D_TOP  zdi4pins2r  [ZDI4PINS2R]
Z_85D_TOP_END  imp_tp_diff  [IMP_TP_1X4_35P]

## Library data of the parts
C59 C129 C153 = cap: CAP,0.1UF,10%,10V,X5R,0201; ALT_SYMBOLS: (CAPC0603X33N,C0201M_FOX,C0201_R4); CLASS: DISCRETE; DPN: MNN3J; Dielectric Type: X5R; Lead Free: Yes; Lifecycle Phase: A Revision; Manufacturer: DARFON ELECTRONICS CORP; Manufacturer PN: C0603X5R104KDT; Package Height: 0.33 MM; Package Size: 0201; Package Type: SMD; Part Number: MNN3J; ROOM: BRD1; Rev: A00-00; Tolerance: 10%; Voltage: 10V
C60 = cap: CAP,1UF,10%,50V,X5R,0603; CLASS: DISCRETE; DPN: 15D2J; Dielectric Type: X5R; Lead Free: Yes; Lifecycle Phase: A Revision; Manufacturer: MURATA ERIE; Manufacturer PN: GRM188R61H105KAALD; Package Height: 40 MIL; Package Size: 0603; Package Type: SMD; Part Number: 15D2J; Rev: A00-00; Tolerance: 10%; Voltage: 50V
DS3 = ps2801: IC,PS2801,SOP4,OPTOCOUPLER; CLASS: IC; Manufacturer: CALIFORNIA EASTERN LABORATORIE; Manufacturer PN: PS2801-1; Package Height: 2.3 MM; Package Size: SOP4; Package Type: SMD; Part Number: 3TTYD
P10 = g_2x1: CON,HDR,1X2,M,.1X.32,S,T,U,TH; CLASS: IO; Manufacturer: FCI; Manufacturer PN: 78511-402HLF; Package Height: 426 MIL; Package Size: HDR1X2; Package Type: TH; Part Number: RD013
R102 = res: RES,5.1K,1/16W,1%,THKFLM,0402; CLASS: DISCRETE; DPN: X9651; Lead Free: Yes; Lifecycle Phase: A Revision; Manufacturer: SEI ELECTRONICS INC; Manufacturer PN: RMCF 1/16S 5101 1%; Material: Thick Film; Package Height: 16 MIL; Package Size: 0402; Package Type: SMD; Part Number: X9651; Rated Power: 62.5mW; Rev: A00-00; Tolerance: 1%
R103 = res: RES,10K,1/16W,1%,THKFLM,0402; DEVICE: 090729121122; Part Number: N1256; ROOM: BRD1; Rated Power: 62.5mW; TOLERANCE: 1%
R104-R108 = res: RES,100K,1/16W,5%,THKFLM,0402; CLASS: DISCRETE; DPN: 92259; Lead Free: Yes; Lifecycle Phase: A Revision; Manufacturer: KOA; Manufacturer PN: RK73B1ETTP104J; Material: Thick Film; Package Height: 16 MIL; Package Size: 0402; Package Type: SMD; Part Number: 92259; Rated Power: 62.5mW; Rev: A00-00; Tolerance: 5%
R118 = res: RES,0,1/20W,5%,THKFLM,0201; ALT_SYMBOLS: (R0201_R4,R0201M_FOX); CLASS: DISCRETE; DPN: YY941; Lead Free: Yes; Lifecycle Phase: A Revision; Manufacturer: KOA; Manufacturer PN: RK73Z1HTQTC; Material: Thick Film; Package Height: 0.33 MM; Package Size: 0201; Package Type: SMD; Part Number: YY941; ROOM: OCPCONN; Rated Power: 50mW; Rev: A00-00; Tolerance: 5%
R185 = res: RES,4.7K,1/16W,5%,THKFLM,0402; CLASS: DISCRETE; DPN: N5300; Lead Free: Yes; Lifecycle Phase: A Revision; Manufacturer: KOA; Manufacturer PN: RK73B1ETTP472J; Material: Thick Film; Package Height: 16 MIL; Package Size: 0402; Package Type: SMD; Part Number: N5300; Rated Power: 62.5mW; Rev: A00-00; Tolerance: 5%
R218 = res: RES,787,1/16W,1%,THKFLM,0402; CLASS: DISCRETE; DPN: H8997; Lead Free: Yes; Lifecycle Phase: A Revision; Manufacturer: SEI ELECTRONICS INC; Manufacturer PN: RMCF0402FT787R; Material: Thick Film; Package Height: 16 MIL; Package Size: 0402; Package Type: SMD; Part Number: U024H; Rated Power: 62.5mW; Rev: A00-00; Tolerance: 1%
SW_RST = sw3psmra_spdt: SWT,PB,SPDT,ON-MOM,SMT; CLASS: DISCRETE; DPN: GC8VG; Lead Free: Yes; Lifecycle Phase: X Revision; Manufacturer: C&K; Manufacturer PN: EP12SD1SAPE; Package Height: 5.08 MM; Package Type: SMD; Part Number: GC8VG; ROOM: BRD1; Rev: X00-00; Switch Configuration: SPDT; Switch Type: PUSHBUTTON
U11-U13 U15 = max811: IC,811,SOT143,2.63V; CLASS: IC; DPN: 2E549; Lead Free: No; Lifecycle Phase: A Revision; Manufacturer: IMP; Manufacturer PN: IMP811REUS-T; Package Height: 1.22 MM; Package Size: SOT143; Package Type: SMD; Part Number: 2E549; Rev: A00-00; Voltage: 2.63V
U14 U16 = g_and_1slot_a1_b2: IC,SN74LVC1G08,SOT23,AND; CLASS: IC; DPN: JM641; Lead Free: Yes; Lifecycle Phase: A Revision; Manufacturer: FAIRCHILD; Manufacturer PN: NC7SZ08M5X; Package Height: 1.45 MM; Package Size: SOT23; Package Type: SMD; Part Number: JM641; Rev: A00-00
U21 = g_inv_1slot_nc1_a2: IC,7SZ14,SOT353,INVERTER; CLASS: IC; Manufacturer: FAIRCHILD; Manufacturer PN: NC7SZ14P5X; Package Height: 1.1 MM; Package Size: SOT353; Package Type: SMD; Part Number: DT962
P_CPU_OCP_0_N1 P_CPU_OCP_0_P1 P_CPU_OCP_1_N1 P_CPU_OCP_1_P1 P_CPU_OCP_2_N1 P_CPU_OCP_2_P1 P_CPU_OCP_3_N1 P_CPU_OCP_3_P1 P_CPU_OCP_4_N P_CPU_OCP_4_P P_CPU_OCP_5_N P_CPU_OCP_5_P P_CPU_OCP_6_N P_CPU_OCP_6_P P_CPU_OCP_7_N P_CPU_OCP_7_P P_CPU_OCP_8_N P_CPU_OCP_8_P P_CPU_OCP_9_N P_CPU_OCP_9_P P_CPU_OCP_10_N P_CPU_OCP_10_P P_CPU_OCP_11_N P_CPU_OCP_11_P P_CPU_OCP_12_N P_CPU_OCP_12_P P_CPU_OCP_13_N P_CPU_OCP_13_P P_CPU_OCP_14_N P_CPU_OCP_14_P P_CPU_OCP_15_N P_CPU_OCP_15_P = g_jack_1: CON,HDR,COAXIAL,F,G,SMT; ALT_SYMBOLS: (96_mmpx-50-0-3_l6_casea); DPN: WD7FW; Lead Free: Yes; Lifecycle Phase: Preliminary; Manufacturer: HUBBLE INC; Manufacturer PN: 96_MMPX-50-0-3/111_N_; Package Height: 247 MIL; Package Type: SMD/TH; Part Number: 50Y9H; ROOM: BRD1; Rev: Introductory
P_CAL_CPU_OCP_0_N P_CAL_CPU_OCP_0_P P_OCP_CPU_0_N1 P_OCP_CPU_0_P1 P_OCP_CPU_1_N1 P_OCP_CPU_1_P1 P_OCP_CPU_2_N1 P_OCP_CPU_2_P1 P_OCP_CPU_3_N1 P_OCP_CPU_3_P1 P_OCP_CPU_4_N P_OCP_CPU_4_P4 P_OCP_CPU_5_N P_OCP_CPU_5_P P_OCP_CPU_6_N P_OCP_CPU_6_P P_OCP_CPU_7_N P_OCP_CPU_7_P P_OCP_CPU_8_N P_OCP_CPU_8_P P_OCP_CPU_9_N P_OCP_CPU_9_P P_OCP_CPU_10_N P_OCP_CPU_10_P P_OCP_CPU_11_N P_OCP_CPU_11_P P_OCP_CPU_12_N P_OCP_CPU_12_P P_OCP_CPU_13_N P_OCP_CPU_13_P P_OCP_CPU_14_N P_OCP_CPU_14_P P_OCP_CPU_15_N P_OCP_CPU_15_P P_SMA_BOT_5IN_DN_1 P_SMA_BOT_5IN_DN_2 P_SMA_BOT_5IN_DP_1 P_SMA_BOT_5IN_DP_2 P_SMA_BOT_10IN_DN_1 P_SMA_BOT_10IN_DN_2 P_SMA_BOT_10IN_DP_1 P_SMA_BOT_10IN_DP_2 P_SMA_TOP_5IN_DN_1 P_SMA_TOP_5IN_DN_2 P_SMA_TOP_5IN_DP_1 P_SMA_TOP_5IN_DP_2 P_SMA_TOP_10IN_DN_1 P_SMA_TOP_10IN_DN_2 P_SMA_TOP_10IN_DP_1 P_SMA_TOP_10IN_DP_2 = g_jack_0: CON,HDR,COAXIAL,F,G,SMT; ALT_SYMBOLS: (96_mmpx-50-0-3_l6_casea); Manufacturer: HUBBLE INC; Manufacturer PN: 96_MMPX-50-0-3/111_N_; Package Height: 247 MIL; Package Type: SMD/TH; Part Number: 50Y9H
C125-C128 = cap: CAP,0.056UF,10%,10V,X7R,0402; CLASS: DISCRETE; DPN: KN9YT; Dielectric Type: X7R; Lead Free: Yes; Lifecycle Phase: Preliminary; Manufacturer: SAMSUNG; Manufacturer PN: CL05B563KP5NNNC; Package Height: 24 MIL; Package Size: 0402; Package Type: SMD; Part Number: KN9YT; ROOM: CAL; Rev: Introductory; SUB: NP; Tolerance: 10%; Voltage: 10V
J_S2D_BOT J_S2D_TOP = tp3_pprobeb_sm-empty: PROBE,3-PIN,SMT,W/ALIGN PINS; BOM_IGNORE: TRUE; CLASS: DISCRETE; DPN: 00000; Lead Free: N/A; Lifecycle Phase: N/A; Package Height: 10 MIL; Package Type: SMD; Part Number: 110408130004; Rev: N/A
P_OCPEDGE = c84edg_amp: [EDGE CARD]CON,EC,168,.6MM,S,G,ST; ALT_SYMBOLS: (CON_AMP_EDGE_ME101681340131X_alt); BOM_IGNORE: TRUE; CLASS: IO; Connector Type: EDGE-CARD; DPN: 00000_7HYMF; Lead Free: N/A; Lifecycle Phase: N/A; Package Height: 0.98 MM; Package Type: EDGE-CARD; Part Number: 7HYMF|EDG; Rev: N/A
R183 R184 = res: RES,4.7K,1/16W,5%,THKFLM,0402; CLASS: DISCRETE; DPN: N5300; Lead Free: Yes; Lifecycle Phase: A Revision; Manufacturer: KOA; Manufacturer PN: RK73B1ETTP472J; Material: Thick Film; Package Height: 16 MIL; Package Size: 0402; Package Type: SMD; Part Number: N5300; ROOM: CAL; Rated Power: 62.5mW; Rev: A00-00; SUB: NP; Tolerance: 5%
Z_42.5_TOP Z_50_BOT Z_50_TOP = zse3pins2r: IMPEDENCE COUPON 3 PIN; BOM_IGNORE: TRUE; CLASS: DISCRETE; DPN: 00000; Lead Free: N/A; Lifecycle Phase: N/A; Package Height: 1 MIL; Package Type: TH; Part Number: 090730100157; Rev: N/A
Z_42.5_TOP_END Z_50_BOT_END Z_50_TOP_END = imp_tp_se: IMPEDENCE TEST POINT 25RD12 SINGLE ENDED 1X3; BOM_IGNORE: TRUE; CLASS: DISCRETE; DPN: 00000; Lead Free: N/A; Lifecycle Phase: N/A; Package Height: 1 MIL; Package Type: TH; Part Number: 090730100116; Rev: N/A
Z_85D_BOT Z_85D_TOP = zdi4pins2r: IMPEDENCE COUPON 4 PIN; DEVICE: 090730100156; Part Number: 00000; TAG2: COUPON TEST
Z_85D_BOT_END Z_85D_TOP_END = imp_tp_diff: IMPEDENCE TEST POINT 25RD12 DIFFERENTIAL 1X4; DEVICE: 090730100117; Part Number: 00000; TAG1: IMPEDANCE DIFFERENTIAL; TAG2: TEST POINT

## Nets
GND: C59.1 C60.1 C129.1 C153.1 DS3.3(E) P_CPU_OCP_0_N1.2(MH1) P_CPU_OCP_0_N1.3(MH2) P_CPU_OCP_0_N1.4(MH3) P_CPU_OCP_0_N1.5(MH4) P_CPU_OCP_0_N1.6(MH6) P_CPU_OCP_0_P1.2(MH1) P_CPU_OCP_0_P1.3(MH2) P_CPU_OCP_0_P1.4(MH3) P_CPU_OCP_0_P1.5(MH4) P_CPU_OCP_0_P1.6(MH6) P_CPU_OCP_1_N1.2(MH1) P_CPU_OCP_1_N1.3(MH2) P_CPU_OCP_1_N1.4(MH3) P_CPU_OCP_1_N1.5(MH4) P_CPU_OCP_1_N1.6(MH6) P_CPU_OCP_1_P1.2(MH1) P_CPU_OCP_1_P1.3(MH2) P_CPU_OCP_1_P1.4(MH3) P_CPU_OCP_1_P1.5(MH4) P_CPU_OCP_1_P1.6(MH6) P_CPU_OCP_2_N1.2(MH1) P_CPU_OCP_2_N1.3(MH2) P_CPU_OCP_2_N1.4(MH3) P_CPU_OCP_2_N1.5(MH4) P_CPU_OCP_2_N1.6(MH6) P_CPU_OCP_2_P1.2(MH1) P_CPU_OCP_2_P1.3(MH2) P_CPU_OCP_2_P1.4(MH3) P_CPU_OCP_2_P1.5(MH4) P_CPU_OCP_2_P1.6(MH6) P_CPU_OCP_3_N1.2(MH1) P_CPU_OCP_3_N1.3(MH2) P_CPU_OCP_3_N1.4(MH3) P_CPU_OCP_3_N1.5(MH4) P_CPU_OCP_3_N1.6(MH6) P_CPU_OCP_3_P1.2(MH1) P_CPU_OCP_3_P1.3(MH2) P_CPU_OCP_3_P1.4(MH3) P_CPU_OCP_3_P1.5(MH4) P_CPU_OCP_3_P1.6(MH6) P_CPU_OCP_4_N.2(MH1) P_CPU_OCP_4_N.3(MH2) P_CPU_OCP_4_N.4(MH3) P_CPU_OCP_4_N.5(MH4) P_CPU_OCP_4_N.6(MH6) P_CPU_OCP_4_P.2(MH1) P_CPU_OCP_4_P.3(MH2) P_CPU_OCP_4_P.4(MH3) P_CPU_OCP_4_P.5(MH4) P_CPU_OCP_4_P.6(MH6) P_CPU_OCP_5_N.2(MH1) P_CPU_OCP_5_N.3(MH2) P_CPU_OCP_5_N.4(MH3) P_CPU_OCP_5_N.5(MH4) P_CPU_OCP_5_N.6(MH6) P_CPU_OCP_5_P.2(MH1) P_CPU_OCP_5_P.3(MH2) P_CPU_OCP_5_P.4(MH3) P_CPU_OCP_5_P.5(MH4) P_CPU_OCP_5_P.6(MH6) P_CPU_OCP_6_N.2(MH1) P_CPU_OCP_6_N.3(MH2) P_CPU_OCP_6_N.4(MH3) P_CPU_OCP_6_N.5(MH4) P_CPU_OCP_6_N.6(MH6) P_CPU_OCP_6_P.2(MH1) P_CPU_OCP_6_P.3(MH2) P_CPU_OCP_6_P.4(MH3) P_CPU_OCP_6_P.5(MH4) P_CPU_OCP_6_P.6(MH6) P_CPU_OCP_7_N.2(MH1) P_CPU_OCP_7_N.3(MH2) P_CPU_OCP_7_N.4(MH3) P_CPU_OCP_7_N.5(MH4) P_CPU_OCP_7_N.6(MH6) P_CPU_OCP_7_P.2(MH1) P_CPU_OCP_7_P.3(MH2) P_CPU_OCP_7_P.4(MH3) P_CPU_OCP_7_P.5(MH4) P_CPU_OCP_7_P.6(MH6) P_CPU_OCP_8_N.2(MH1) P_CPU_OCP_8_N.3(MH2) P_CPU_OCP_8_N.4(MH3) P_CPU_OCP_8_N.5(MH4) P_CPU_OCP_8_N.6(MH6) P_CPU_OCP_8_P.2(MH1) P_CPU_OCP_8_P.3(MH2) P_CPU_OCP_8_P.4(MH3) P_CPU_OCP_8_P.5(MH4) P_CPU_OCP_8_P.6(MH6) P_CPU_OCP_9_N.2(MH1) P_CPU_OCP_9_N.3(MH2) P_CPU_OCP_9_N.4(MH3) P_CPU_OCP_9_N.5(MH4) P_CPU_OCP_9_N.6(MH6) P_CPU_OCP_9_P.2(MH1) P_CPU_OCP_9_P.3(MH2) P_CPU_OCP_9_P.4(MH3) P_CPU_OCP_9_P.5(MH4) P_CPU_OCP_9_P.6(MH6) P_CPU_OCP_10_N.2(MH1) P_CPU_OCP_10_N.3(MH2) P_CPU_OCP_10_N.4(MH3) P_CPU_OCP_10_N.5(MH4) P_CPU_OCP_10_N.6(MH6) P_CPU_OCP_10_P.2(MH1) P_CPU_OCP_10_P.3(MH2) P_CPU_OCP_10_P.4(MH3) P_CPU_OCP_10_P.5(MH4) P_CPU_OCP_10_P.6(MH6) P_CPU_OCP_11_N.2(MH1) P_CPU_OCP_11_N.3(MH2) P_CPU_OCP_11_N.4(MH3) P_CPU_OCP_11_N.5(MH4) P_CPU_OCP_11_N.6(MH6) P_CPU_OCP_11_P.2(MH1) P_CPU_OCP_11_P.3(MH2) P_CPU_OCP_11_P.4(MH3) P_CPU_OCP_11_P.5(MH4) P_CPU_OCP_11_P.6(MH6) P_CPU_OCP_12_N.2(MH1) P_CPU_OCP_12_N.3(MH2) P_CPU_OCP_12_N.4(MH3) P_CPU_OCP_12_N.5(MH4) P_CPU_OCP_12_N.6(MH6) P_CPU_OCP_12_P.2(MH1) P_CPU_OCP_12_P.3(MH2) P_CPU_OCP_12_P.4(MH3) P_CPU_OCP_12_P.5(MH4) P_CPU_OCP_12_P.6(MH6) P_CPU_OCP_13_N.2(MH1) P_CPU_OCP_13_N.3(MH2) P_CPU_OCP_13_N.4(MH3) P_CPU_OCP_13_N.5(MH4) P_CPU_OCP_13_N.6(MH6) P_CPU_OCP_13_P.2(MH1) P_CPU_OCP_13_P.3(MH2) P_CPU_OCP_13_P.4(MH3) P_CPU_OCP_13_P.5(MH4) P_CPU_OCP_13_P.6(MH6) P_CPU_OCP_14_N.2(MH1) P_CPU_OCP_14_N.3(MH2) P_CPU_OCP_14_N.4(MH3) P_CPU_OCP_14_N.5(MH4) P_CPU_OCP_14_N.6(MH6) P_CPU_OCP_14_P.2(MH1) P_CPU_OCP_14_P.3(MH2) P_CPU_OCP_14_P.4(MH3) P_CPU_OCP_14_P.5(MH4) P_CPU_OCP_14_P.6(MH6) P_CPU_OCP_15_N.2(MH1) P_CPU_OCP_15_N.3(MH2) P_CPU_OCP_15_N.4(MH3) P_CPU_OCP_15_N.5(MH4) P_CPU_OCP_15_N.6(MH6) P_CPU_OCP_15_P.2(MH1) P_CPU_OCP_15_P.3(MH2) P_CPU_OCP_15_P.4(MH3) P_CPU_OCP_15_P.5(MH4) P_CPU_OCP_15_P.6(MH6) P_OCP_CPU_0_N1.2 P_OCP_CPU_0_N1.3 P_OCP_CPU_0_N1.4 P_OCP_CPU_0_N1.5 P_OCP_CPU_0_N1.6 P_OCP_CPU_0_P1.2 P_OCP_CPU_0_P1.3 P_OCP_CPU_0_P1.4 P_OCP_CPU_0_P1.5 P_OCP_CPU_0_P1.6 P_OCP_CPU_1_N1.2 P_OCP_CPU_1_N1.3 P_OCP_CPU_1_N1.4 P_OCP_CPU_1_N1.5 P_OCP_CPU_1_N1.6 P_OCP_CPU_1_P1.2 P_OCP_CPU_1_P1.3 P_OCP_CPU_1_P1.4 P_OCP_CPU_1_P1.5 P_OCP_CPU_1_P1.6 P_OCP_CPU_2_N1.2 P_OCP_CPU_2_N1.3 P_OCP_CPU_2_N1.4 P_OCP_CPU_2_N1.5 P_OCP_CPU_2_N1.6 P_OCP_CPU_2_P1.2 P_OCP_CPU_2_P1.3 P_OCP_CPU_2_P1.4 P_OCP_CPU_2_P1.5 P_OCP_CPU_2_P1.6 P_OCP_CPU_3_N1.2 P_OCP_CPU_3_N1.3 P_OCP_CPU_3_N1.4 P_OCP_CPU_3_N1.5 P_OCP_CPU_3_N1.6 P_OCP_CPU_3_P1.2 P_OCP_CPU_3_P1.3 P_OCP_CPU_3_P1.4 P_OCP_CPU_3_P1.5 P_OCP_CPU_3_P1.6 P_OCP_CPU_4_N.2 P_OCP_CPU_4_N.3 P_OCP_CPU_4_N.4 P_OCP_CPU_4_N.5 P_OCP_CPU_4_N.6 P_OCP_CPU_4_P4.2 P_OCP_CPU_4_P4.3 P_OCP_CPU_4_P4.4 P_OCP_CPU_4_P4.5 P_OCP_CPU_4_P4.6 P_OCP_CPU_5_N.2 P_OCP_CPU_5_N.3 P_OCP_CPU_5_N.4 P_OCP_CPU_5_N.5 P_OCP_CPU_5_N.6 P_OCP_CPU_5_P.2 P_OCP_CPU_5_P.3 P_OCP_CPU_5_P.4 P_OCP_CPU_5_P.5 P_OCP_CPU_5_P.6 P_OCP_CPU_6_N.2 P_OCP_CPU_6_N.3 P_OCP_CPU_6_N.4 P_OCP_CPU_6_N.5 P_OCP_CPU_6_N.6 P_OCP_CPU_6_P.2 P_OCP_CPU_6_P.3 P_OCP_CPU_6_P.4 P_OCP_CPU_6_P.5 P_OCP_CPU_6_P.6 P_OCP_CPU_7_N.2 P_OCP_CPU_7_N.3 P_OCP_CPU_7_N.4 P_OCP_CPU_7_N.5 P_OCP_CPU_7_N.6 P_OCP_CPU_7_P.2 P_OCP_CPU_7_P.3 P_OCP_CPU_7_P.4 P_OCP_CPU_7_P.5 P_OCP_CPU_7_P.6 P_OCP_CPU_8_N.2 P_OCP_CPU_8_N.3 P_OCP_CPU_8_N.4 P_OCP_CPU_8_N.5 P_OCP_CPU_8_N.6 P_OCP_CPU_8_P.2 P_OCP_CPU_8_P.3 P_OCP_CPU_8_P.4 P_OCP_CPU_8_P.5 P_OCP_CPU_8_P.6 P_OCP_CPU_9_N.2 P_OCP_CPU_9_N.3 P_OCP_CPU_9_N.4 P_OCP_CPU_9_N.5 P_OCP_CPU_9_N.6 P_OCP_CPU_9_P.2 P_OCP_CPU_9_P.3 P_OCP_CPU_9_P.4 P_OCP_CPU_9_P.5 P_OCP_CPU_9_P.6 P_OCP_CPU_10_N.2 P_OCP_CPU_10_N.3 P_OCP_CPU_10_N.4 P_OCP_CPU_10_N.5 P_OCP_CPU_10_N.6 P_OCP_CPU_10_P.2 P_OCP_CPU_10_P.3 P_OCP_CPU_10_P.4 P_OCP_CPU_10_P.5 P_OCP_CPU_10_P.6 P_OCP_CPU_11_N.2 P_OCP_CPU_11_N.3 P_OCP_CPU_11_N.4 P_OCP_CPU_11_N.5 P_OCP_CPU_11_N.6 P_OCP_CPU_11_P.2 P_OCP_CPU_11_P.3 P_OCP_CPU_11_P.4 P_OCP_CPU_11_P.5 P_OCP_CPU_11_P.6 P_OCP_CPU_12_N.2 P_OCP_CPU_12_N.3 P_OCP_CPU_12_N.4 P_OCP_CPU_12_N.5 P_OCP_CPU_12_N.6 P_OCP_CPU_12_P.2 P_OCP_CPU_12_P.3 P_OCP_CPU_12_P.4 P_OCP_CPU_12_P.5 P_OCP_CPU_12_P.6 P_OCP_CPU_13_N.2 P_OCP_CPU_13_N.3 P_OCP_CPU_13_N.4 P_OCP_CPU_13_N.5 P_OCP_CPU_13_N.6 P_OCP_CPU_13_P.2 P_OCP_CPU_13_P.3 P_OCP_CPU_13_P.4 P_OCP_CPU_13_P.5 P_OCP_CPU_13_P.6 P_OCP_CPU_14_N.2 P_OCP_CPU_14_N.3 P_OCP_CPU_14_N.4 P_OCP_CPU_14_N.5 P_OCP_CPU_14_N.6 P_OCP_CPU_14_P.2 P_OCP_CPU_14_P.3 P_OCP_CPU_14_P.4 P_OCP_CPU_14_P.5 P_OCP_CPU_14_P.6 P_OCP_CPU_15_N.2 P_OCP_CPU_15_N.3 P_OCP_CPU_15_N.4 P_OCP_CPU_15_N.5 P_OCP_CPU_15_N.6 P_OCP_CPU_15_P.2 P_OCP_CPU_15_P.3 P_OCP_CPU_15_P.4 P_OCP_CPU_15_P.5 P_OCP_CPU_15_P.6 P_SMA_BOT_5IN_DN_1.2 P_SMA_BOT_5IN_DN_1.3 P_SMA_BOT_5IN_DN_1.4 P_SMA_BOT_5IN_DN_1.5 P_SMA_BOT_5IN_DN_1.6 P_SMA_BOT_5IN_DN_2.2 P_SMA_BOT_5IN_DN_2.3 P_SMA_BOT_5IN_DN_2.4 P_SMA_BOT_5IN_DN_2.5 P_SMA_BOT_5IN_DN_2.6 P_SMA_BOT_5IN_DP_1.2 P_SMA_BOT_5IN_DP_1.3 P_SMA_BOT_5IN_DP_1.4 P_SMA_BOT_5IN_DP_1.5 P_SMA_BOT_5IN_DP_1.6 P_SMA_BOT_5IN_DP_2.2 P_SMA_BOT_5IN_DP_2.3 P_SMA_BOT_5IN_DP_2.4 P_SMA_BOT_5IN_DP_2.5 P_SMA_BOT_5IN_DP_2.6 P_SMA_BOT_10IN_DN_1.2 P_SMA_BOT_10IN_DN_1.3 P_SMA_BOT_10IN_DN_1.4 P_SMA_BOT_10IN_DN_1.5 P_SMA_BOT_10IN_DN_1.6 P_SMA_BOT_10IN_DN_2.2 P_SMA_BOT_10IN_DN_2.3 P_SMA_BOT_10IN_DN_2.4 P_SMA_BOT_10IN_DN_2.5 P_SMA_BOT_10IN_DN_2.6 P_SMA_BOT_10IN_DP_1.2 P_SMA_BOT_10IN_DP_1.3 P_SMA_BOT_10IN_DP_1.4 P_SMA_BOT_10IN_DP_1.5 P_SMA_BOT_10IN_DP_1.6 P_SMA_BOT_10IN_DP_2.2 P_SMA_BOT_10IN_DP_2.3 P_SMA_BOT_10IN_DP_2.4 P_SMA_BOT_10IN_DP_2.5 P_SMA_BOT_10IN_DP_2.6 P_SMA_TOP_5IN_DN_1.2 P_SMA_TOP_5IN_DN_1.3 P_SMA_TOP_5IN_DN_1.4 P_SMA_TOP_5IN_DN_1.5 P_SMA_TOP_5IN_DN_1.6 P_SMA_TOP_5IN_DN_2.2 P_SMA_TOP_5IN_DN_2.3 P_SMA_TOP_5IN_DN_2.4 P_SMA_TOP_5IN_DN_2.5 P_SMA_TOP_5IN_DN_2.6 P_SMA_TOP_5IN_DP_1.2 P_SMA_TOP_5IN_DP_1.3 P_SMA_TOP_5IN_DP_1.4 P_SMA_TOP_5IN_DP_1.5 P_SMA_TOP_5IN_DP_1.6 P_SMA_TOP_5IN_DP_2.2 P_SMA_TOP_5IN_DP_2.3 P_SMA_TOP_5IN_DP_2.4 P_SMA_TOP_5IN_DP_2.5 P_SMA_TOP_5IN_DP_2.6 P_SMA_TOP_10IN_DN_1.2 P_SMA_TOP_10IN_DN_1.3 P_SMA_TOP_10IN_DN_1.4 P_SMA_TOP_10IN_DN_1.5 P_SMA_TOP_10IN_DN_1.6 P_SMA_TOP_10IN_DN_2.2 P_SMA_TOP_10IN_DN_2.3 P_SMA_TOP_10IN_DN_2.4 P_SMA_TOP_10IN_DN_2.5 P_SMA_TOP_10IN_DN_2.6 P_SMA_TOP_10IN_DP_1.2 P_SMA_TOP_10IN_DP_1.3 P_SMA_TOP_10IN_DP_1.4 P_SMA_TOP_10IN_DP_1.5 P_SMA_TOP_10IN_DP_1.6 P_SMA_TOP_10IN_DP_2.2 P_SMA_TOP_10IN_DP_2.3 P_SMA_TOP_10IN_DP_2.4 P_SMA_TOP_10IN_DP_2.5 P_SMA_TOP_10IN_DP_2.6 R103.1 R104.1 R105.1 R106.1 R107.1 R108.1 SW_RST.2 U11.1(GND) U12.1(GND) U13.1(GND) U14.3(GND) U15.1(GND) U16.3(GND) U21.3(GND) ; also on sheet 3 4 5 6 7
GND_SIGNAL: C125.1 C126.1 C127.1 C128.1 J_S2D_BOT.1(GND) J_S2D_TOP.1(GND) P_CAL_CPU_OCP_0_N.2 P_CAL_CPU_OCP_0_N.3 P_CAL_CPU_OCP_0_N.4 P_CAL_CPU_OCP_0_N.5 P_CAL_CPU_OCP_0_N.6 P_CAL_CPU_OCP_0_P.2 P_CAL_CPU_OCP_0_P.3 P_CAL_CPU_OCP_0_P.4 P_CAL_CPU_OCP_0_P.5 P_CAL_CPU_OCP_0_P.6 P_OCPEDGE.A1 P_OCPEDGE.A2 P_OCPEDGE.A3 P_OCPEDGE.A4 P_OCPEDGE.A5 P_OCPEDGE.A6 P_OCPEDGE.A13 P_OCPEDGE.A16 P_OCPEDGE.A19 P_OCPEDGE.A22 P_OCPEDGE.A25 P_OCPEDGE.A28 P_OCPEDGE.A29 P_OCPEDGE.A32 P_OCPEDGE.A35 P_OCPEDGE.A38 P_OCPEDGE.A41 P_OCPEDGE.A43 P_OCPEDGE.A46 P_OCPEDGE.A49 P_OCPEDGE.A52 P_OCPEDGE.A55 P_OCPEDGE.A58 P_OCPEDGE.A61 P_OCPEDGE.A64 P_OCPEDGE.A67 P_OCPEDGE.B13 P_OCPEDGE.B16 P_OCPEDGE.B19 P_OCPEDGE.B22 P_OCPEDGE.B25 P_OCPEDGE.B28 P_OCPEDGE.B29 P_OCPEDGE.B32 P_OCPEDGE.B35 P_OCPEDGE.B38 P_OCPEDGE.B41 P_OCPEDGE.B43 P_OCPEDGE.B46 P_OCPEDGE.B49 P_OCPEDGE.B52 P_OCPEDGE.B55 P_OCPEDGE.B58 P_OCPEDGE.B61 P_OCPEDGE.B64 P_OCPEDGE.B67 P_OCPEDGE.OCP_A6 P_OCPEDGE.OCP_A10 P_OCPEDGE.OCP_A13 P_OCPEDGE.OCP_B10 P_OCPEDGE.OCP_B13 R183.1 R184.1 Z_42.5_TOP.1(RX) Z_42.5_TOP.3(RY) Z_42.5_TOP_END.1 Z_42.5_TOP_END.3 Z_50_BOT.1(RX) Z_50_BOT.3(RY) Z_50_BOT_END.1 Z_50_BOT_END.3 Z_50_TOP.1(RX) Z_50_TOP.3(RY) Z_50_TOP_END.1 Z_50_TOP_END.3 Z_85D_BOT.1(RX) Z_85D_BOT.3(RY) Z_85D_BOT_END.1 Z_85D_BOT_END.4 Z_85D_TOP.1(RX) Z_85D_TOP.3(RY) Z_85D_TOP_END.1 Z_85D_TOP_END.4
ATX_PWR_OK: R102.2 ; also on sheet 7
ATX_PWR_OK_33: R102.1 R103.2 U11.3(~{MR})
AUX_PWR_EN: R104.2 U11.2(~{RESET}) U12.3(~{MR}) ; also on sheet 3
CLKBUF_EN: U14.4(Y) U15.3(~{MR}) U21.2(A) ; also on sheet 5
CLKBUF_EN_DLY: R108.2 R118.1 U15.2(~{RESET})
CLKBUF_EN_N: U21.4(Y) ; also on sheet 6
MAIN_PWR_EN: R105.2 U12.2(~{RESET}) U13.3(~{MR}) ; also on sheet 3 6
MAIN_PWR_EN_DLY: R106.2 U13.2(~{RESET}) U14.1(A)
NIC_PWR_GOOD: R107.2 U14.2(B) ; also on sheet 3
PCIE_RST_BTN_N: U16.4(Y) ; also on sheet 3 7
PCIE_RST_BTN_R: C60.2 R185.1 SW_RST.3 U16.2(B)
PE_CAL_CPU_OCP_0_DN: C125.2 C126.2 P_CAL_CPU_OCP_0_N.1 P_OCPEDGE.B17 R183.2
PE_CAL_CPU_OCP_0_DP: C127.2 C128.2 P_CAL_CPU_OCP_0_P.1 P_OCPEDGE.B18 R184.2
PE_CPU_OCP_0_DN: P_CPU_OCP_0_N1.1 ; also on sheet 3
PE_CPU_OCP_0_DP: P_CPU_OCP_0_P1.1 ; also on sheet 3
PE_CPU_OCP_1_DN: P_CPU_OCP_1_N1.1 ; also on sheet 3
PE_CPU_OCP_1_DP: P_CPU_OCP_1_P1.1 ; also on sheet 3
PE_CPU_OCP_2_DN: P_CPU_OCP_2_N1.1 ; also on sheet 3
PE_CPU_OCP_2_DP: P_CPU_OCP_2_P1.1 ; also on sheet 3
PE_CPU_OCP_3_DN: P_CPU_OCP_3_N1.1 ; also on sheet 3
PE_CPU_OCP_3_DP: P_CPU_OCP_3_P1.1 ; also on sheet 3
PE_CPU_OCP_4_DN: P_CPU_OCP_4_N.1 ; also on sheet 3
PE_CPU_OCP_4_DP: P_CPU_OCP_4_P.1 ; also on sheet 3
PE_CPU_OCP_5_DN: P_CPU_OCP_5_N.1 ; also on sheet 3
PE_CPU_OCP_5_DP: P_CPU_OCP_5_P.1 ; also on sheet 3
PE_CPU_OCP_6_DN: P_CPU_OCP_6_N.1 ; also on sheet 3
PE_CPU_OCP_6_DP: P_CPU_OCP_6_P.1 ; also on sheet 3
PE_CPU_OCP_7_DN: P_CPU_OCP_7_N.1 ; also on sheet 3
PE_CPU_OCP_7_DP: P_CPU_OCP_7_P.1 ; also on sheet 3
PE_CPU_OCP_8_DN: P_CPU_OCP_8_N.1 ; also on sheet 3
PE_CPU_OCP_8_DP: P_CPU_OCP_8_P.1 ; also on sheet 3
PE_CPU_OCP_9_DN: P_CPU_OCP_9_N.1 ; also on sheet 3
PE_CPU_OCP_9_DP: P_CPU_OCP_9_P.1 ; also on sheet 3
PE_CPU_OCP_10_DN: P_CPU_OCP_10_N.1 ; also on sheet 3
PE_CPU_OCP_10_DP: P_CPU_OCP_10_P.1 ; also on sheet 3
PE_CPU_OCP_11_DN: P_CPU_OCP_11_N.1 ; also on sheet 3
PE_CPU_OCP_11_DP: P_CPU_OCP_11_P.1 ; also on sheet 3
PE_CPU_OCP_12_DN: P_CPU_OCP_12_N.1 ; also on sheet 3
PE_CPU_OCP_12_DP: P_CPU_OCP_12_P.1 ; also on sheet 3
PE_CPU_OCP_13_DN: P_CPU_OCP_13_N.1 ; also on sheet 3
PE_CPU_OCP_13_DP: P_CPU_OCP_13_P.1 ; also on sheet 3
PE_CPU_OCP_14_DN: P_CPU_OCP_14_N.1 ; also on sheet 3
PE_CPU_OCP_14_DP: P_CPU_OCP_14_P.1 ; also on sheet 3
PE_CPU_OCP_15_DN: P_CPU_OCP_15_N.1 ; also on sheet 3
PE_CPU_OCP_15_DP: P_CPU_OCP_15_P.1 ; also on sheet 3
PE_OCP_CPU_0_DN: P_OCP_CPU_0_N1.1 ; also on sheet 3
PE_OCP_CPU_0_DP: P_OCP_CPU_0_P1.1 ; also on sheet 3
PE_OCP_CPU_1_DN: P_OCP_CPU_1_N1.1 ; also on sheet 3
PE_OCP_CPU_1_DP: P_OCP_CPU_1_P1.1 ; also on sheet 3
PE_OCP_CPU_2_DN: P_OCP_CPU_2_N1.1 ; also on sheet 3
PE_OCP_CPU_2_DP: P_OCP_CPU_2_P1.1 ; also on sheet 3
PE_OCP_CPU_3_DN: P_OCP_CPU_3_N1.1 ; also on sheet 3
PE_OCP_CPU_3_DP: P_OCP_CPU_3_P1.1 ; also on sheet 3
PE_OCP_CPU_4_DN: P_OCP_CPU_4_N.1 ; also on sheet 3
PE_OCP_CPU_4_DP: P_OCP_CPU_4_P4.1 ; also on sheet 3
PE_OCP_CPU_5_DN: P_OCP_CPU_5_N.1 ; also on sheet 3
PE_OCP_CPU_5_DP: P_OCP_CPU_5_P.1 ; also on sheet 3
PE_OCP_CPU_6_DN: P_OCP_CPU_6_N.1 ; also on sheet 3
PE_OCP_CPU_6_DP: P_OCP_CPU_6_P.1 ; also on sheet 3
PE_OCP_CPU_7_DN: P_OCP_CPU_7_N.1 ; also on sheet 3
PE_OCP_CPU_7_DP: P_OCP_CPU_7_P.1 ; also on sheet 3
PE_OCP_CPU_8_DN: P_OCP_CPU_8_N.1 ; also on sheet 3
PE_OCP_CPU_8_DP: P_OCP_CPU_8_P.1 ; also on sheet 3
PE_OCP_CPU_9_DN: P_OCP_CPU_9_N.1 ; also on sheet 3
PE_OCP_CPU_9_DP: P_OCP_CPU_9_P.1 ; also on sheet 3
PE_OCP_CPU_10_DN: P_OCP_CPU_10_N.1 ; also on sheet 3
PE_OCP_CPU_10_DP: P_OCP_CPU_10_P.1 ; also on sheet 3
PE_OCP_CPU_11_DN: P_OCP_CPU_11_N.1 ; also on sheet 3
PE_OCP_CPU_11_DP: P_OCP_CPU_11_P.1 ; also on sheet 3
PE_OCP_CPU_12_DN: P_OCP_CPU_12_N.1 ; also on sheet 3
PE_OCP_CPU_12_DP: P_OCP_CPU_12_P.1 ; also on sheet 3
PE_OCP_CPU_13_DN: P_OCP_CPU_13_N.1 ; also on sheet 3
PE_OCP_CPU_13_DP: P_OCP_CPU_13_P.1 ; also on sheet 3
PE_OCP_CPU_14_DN: P_OCP_CPU_14_N.1 ; also on sheet 3
PE_OCP_CPU_14_DP: P_OCP_CPU_14_P.1 ; also on sheet 3
PE_OCP_CPU_15_DN: P_OCP_CPU_15_N.1 ; also on sheet 3
PE_OCP_CPU_15_DP: P_OCP_CPU_15_P.1 ; also on sheet 3
SET2DIL_85_BOT: J_S2D_BOT.2 J_S2D_BOT.3
SET2DIL_85_TOP: J_S2D_TOP.2 J_S2D_TOP.3
SMA_5IN_BOT_DN: P_SMA_BOT_5IN_DN_1.1 P_SMA_BOT_5IN_DN_2.1
SMA_5IN_BOT_DP: P_SMA_BOT_5IN_DP_1.1 P_SMA_BOT_5IN_DP_2.1
SMA_5IN_TOP_DN: P_SMA_TOP_5IN_DN_1.1 P_SMA_TOP_5IN_DN_2.1
SMA_5IN_TOP_DP: P_SMA_TOP_5IN_DP_1.1 P_SMA_TOP_5IN_DP_2.1
SMA_10IN_BOT_DN: P_SMA_BOT_10IN_DN_1.1 P_SMA_BOT_10IN_DN_2.1
SMA_10IN_BOT_DP: P_SMA_BOT_10IN_DP_1.1 P_SMA_BOT_10IN_DP_2.1
SMA_10IN_TOP_DN: P_SMA_TOP_10IN_DN_1.1 P_SMA_TOP_10IN_DN_2.1
SMA_10IN_TOP_DP: P_SMA_TOP_10IN_DP_1.1 P_SMA_TOP_10IN_DP_2.1
V_3P3: C59.2 C129.2 C153.2 R185.2 U11.4(VCC) U12.4(VCC) U13.4(VCC) U14.5(VCC) U15.4(VCC) U16.5(VCC) U21.5(VCC) ; also on sheet 3 4 5 6 7
Z_42.5_TOP: Z_42.5_TOP.2(+) Z_42.5_TOP_END.2
Z_50_BOT: Z_50_BOT.2(+) Z_50_BOT_END.2
Z_50_TOP: Z_50_TOP.2(+) Z_50_TOP_END.2
Z_85D_BOT_DN: Z_85D_BOT.4(-) Z_85D_BOT_END.3
Z_85D_BOT_DP: Z_85D_BOT.2(+) Z_85D_BOT_END.2
Z_85D_TOP_DN: Z_85D_TOP.4(-) Z_85D_TOP_END.3
Z_85D_TOP_DP: Z_85D_TOP.2(+) Z_85D_TOP_END.2
N16884462: R118.2 U16.1(A)
N17073446: DS3.1(A) R218.1
N17073448: P10.2 R218.2
N17073464: DS3.2(C) P10.1

Not connected (* = marked no-connect by the designer): DS3 4(COL); P_OCPEDGE A7 A8 A9 A10 A11 A12 A14 A15 A17 A18 A20 A21 A23 A24 A26 A27 A30 A31 A33 A34 A36 A37 A39 A40 A42 A44 A45 A47 A48 A50 A51 A53 A54 A56 A57 A59 A60 A62 A63 A65 A66 A68 A69 A70 B1 B2 B3 B4 B5 B6 B7 B8 B9 B10 B11 B12 B14 B15 B20 B21 B23 B24 B26 B27 B30 B31 B33 B34 B36 B37 B39 B40 B42 B44 B45 B47 B48 B50 B51 B53 B54 B56 B57 B59 B60 B62 B63 B65 B66 B68 B69 B70 OCP_A1 OCP_A2 OCP_A3 OCP_A4 OCP_A5 OCP_A7 OCP_A8 OCP_A9 OCP_A11 OCP_A12 OCP_A14 OCP_B1 OCP_B2 OCP_B3 OCP_B4 OCP_B5 OCP_B6 OCP_B7 OCP_B8 OCP_B9 OCP_B11 OCP_B12 OCP_B14; SW_RST 1*; U21 1(NC)*

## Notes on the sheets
sheet 8
- POWER SEQUENCE
- MAX811 Reset Active Timeout Period Trp: 140 - 560ms
- Reset Button
- RESET AUTOMATION CONNECTOR
sheet 9
- OCP TX
- PCIe Lanes 0-3
- OCP RX
sheet 10
- PCIe Lanes 4-7
- OCP RX
- OCP TX
sheet 11
- PCIe Lanes 8-11
- OCP RX
- OCP TX
sheet 12
- PCIe Lanes 12-15
- OCP RX
- OCP TX
sheet 13
- MMPXs (5 in and 10 in) - Breakaway Tab 2
sheet 14
- CBB CALIBRATION BOARD - Breakaway Tab 1
- Impedance Coupons - Breakaway Tab 1
  ( 6 inches)
- SET 2 DIL Coupons -
  Breakaway Tab 1
